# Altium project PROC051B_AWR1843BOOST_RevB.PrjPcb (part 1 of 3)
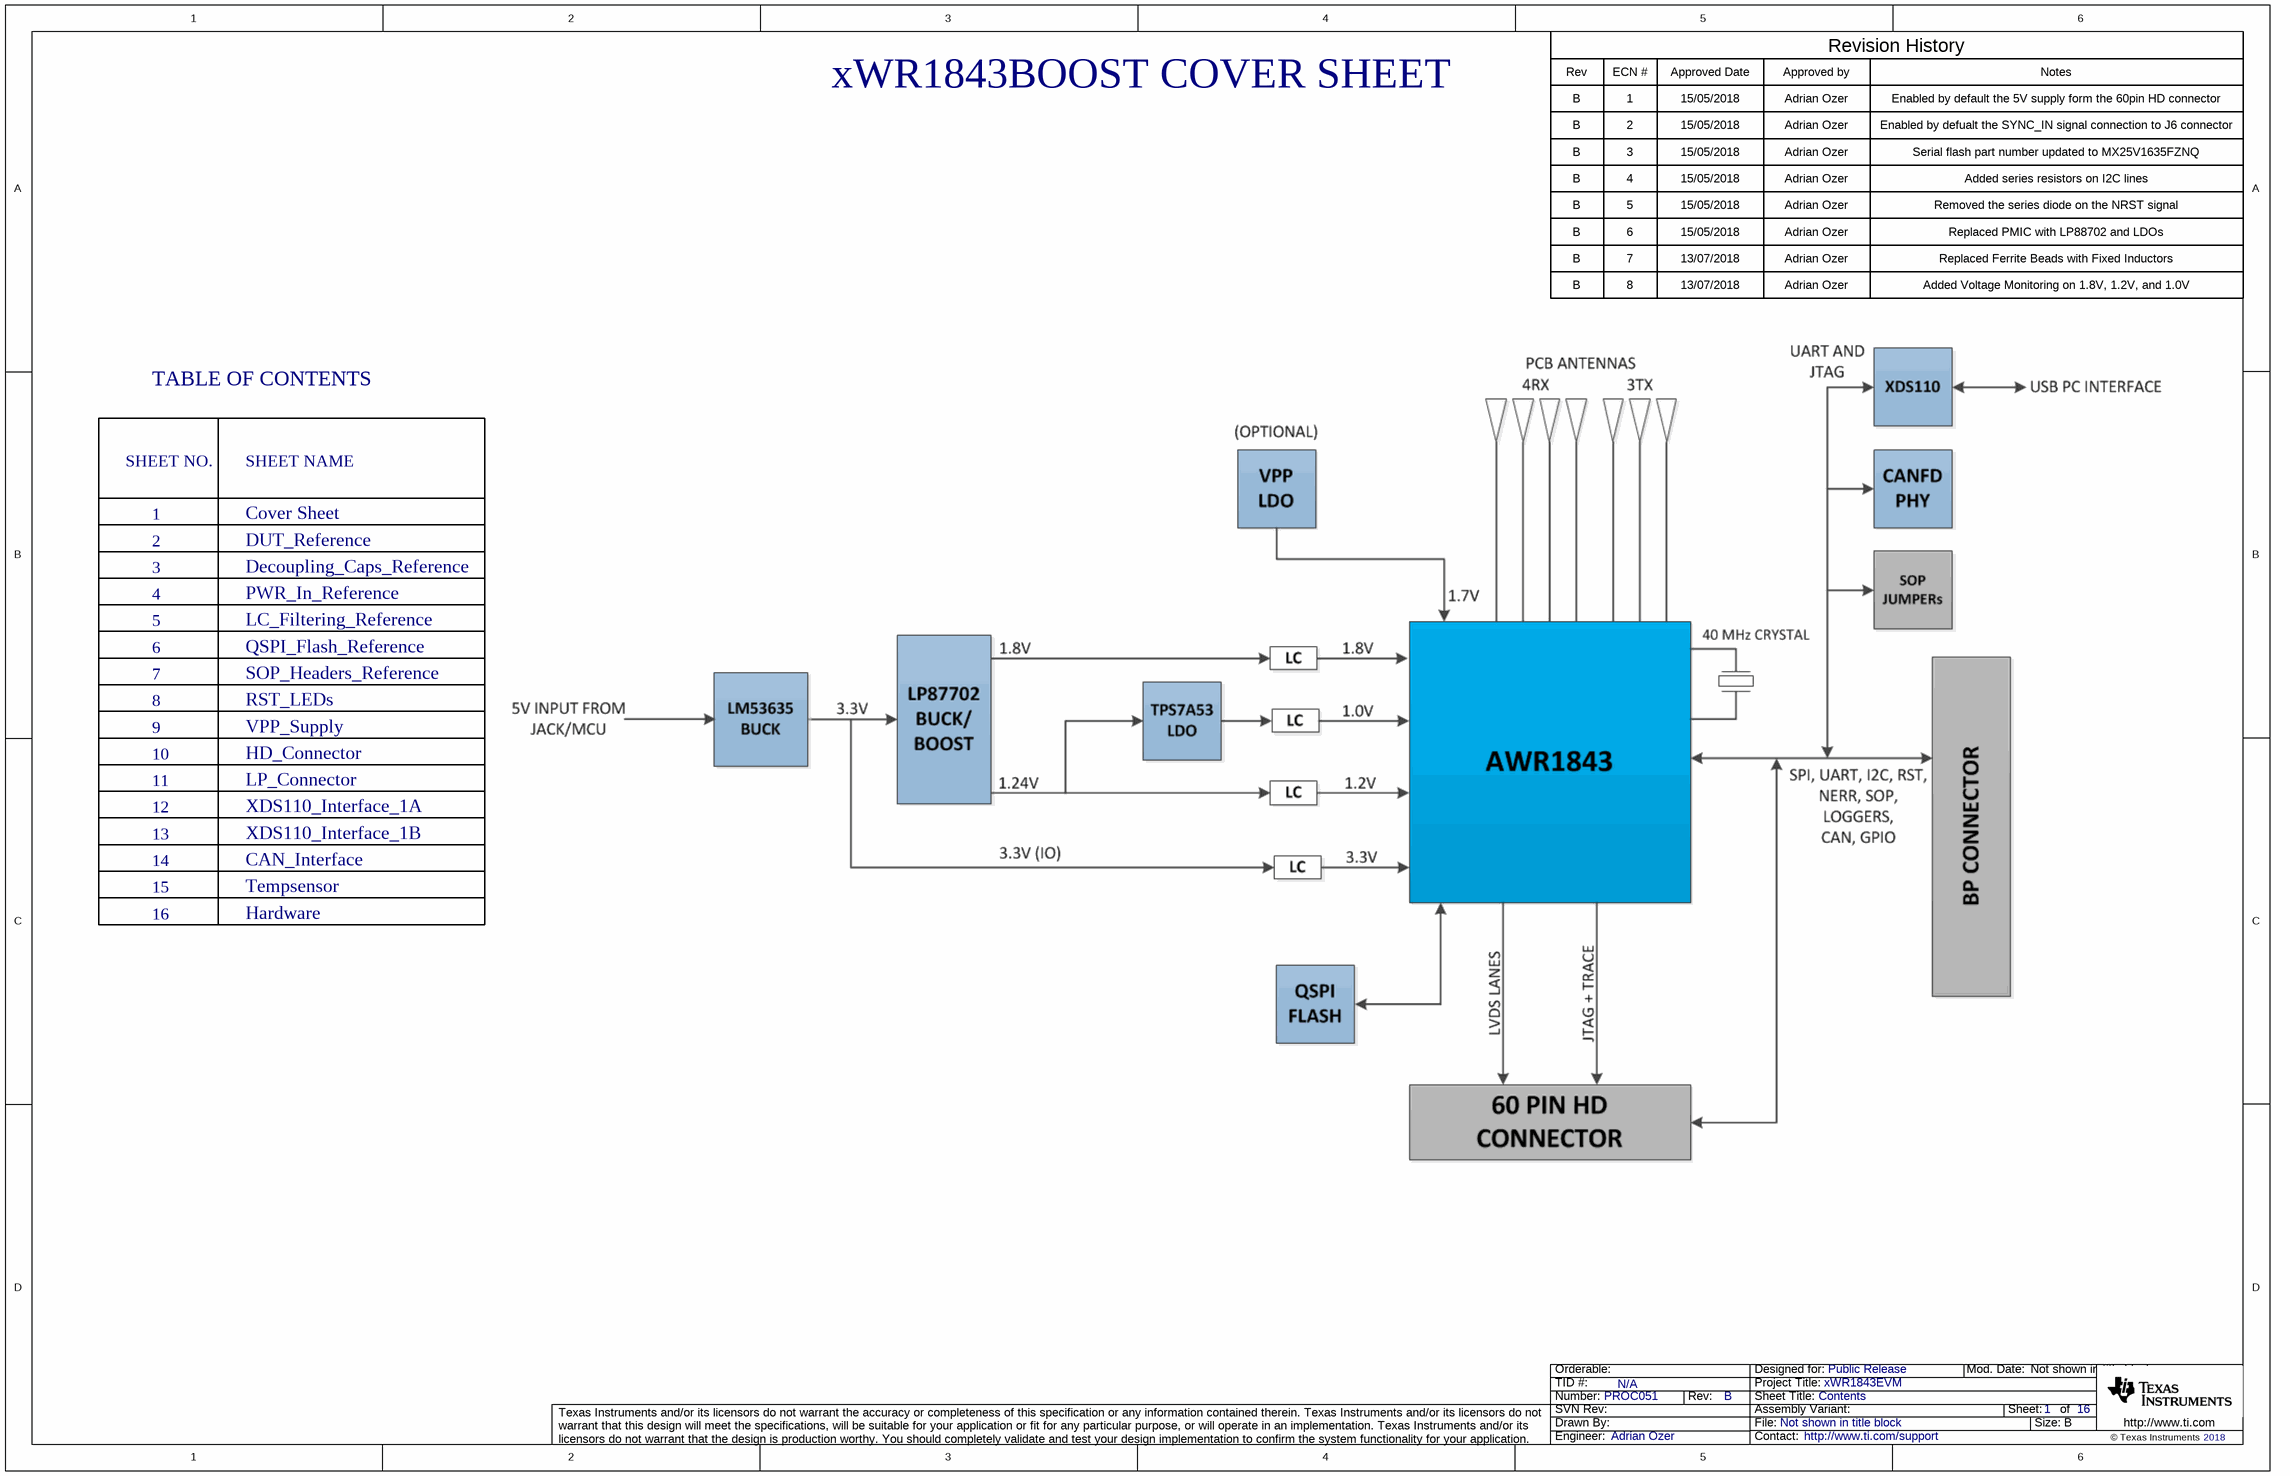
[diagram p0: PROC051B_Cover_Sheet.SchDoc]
CopyrightYear: 2018; PCB_Layout: TESSOLVE; PCB_Rev: B; PRJ_Customer: Public Release; PRJ_Engineer: Adrian Ozer; PRJ_Number: PROC051; PRJ_Title: xWR1843EVM; SCH_Rev: B; TechSupport: http://www.ti.com/support; TID: N/A
16 sheets, 379 parts. Net scope: flat (ports and power ports of the same name join across sheets).
Board file: PROC051B_PCB.PcbDoc
Sheets:
  PROC051B_Cover_Sheet.SchDoc
  PROC051B_DUT_Reference.SchDoc
  PROC051B_Decoupling_Caps_Reference.SchDoc
  PROC051B_PWR_In_Reference.SchDoc
  PROC051B_LC_Filtering_Reference.SchDoc
  PROC051B_QSPI_Flash_Reference.SchDoc
  PROC051B_SOP_Headers_Reference.SchDoc
  PROC051B_RST_LEDs.SchDoc
  PROC051B_VPP_Supply.SchDoc
  PROC051B_HD Connector.SchDoc
  PROC051B_LP Connector.SchDoc
  PROC051B_XDS110 Interface_1A.SchDoc
  PROC051B_XDS110 Interface_1B.SchDoc
  PROC051B_CAN_Interface.SchDoc
  PROC051B_Tempsensor.SchDoc
  PROC051B_Hardware.SchDoc

## Sheet PROC051B_Cover_Sheet.SchDoc: Contents
size 431 x 279 mm; Date: Not shown in title block; ApprovedBy: Not shown in title block; CheckedBy: Not shown in title block; Author: Not shown in title block; CompanyName: Not shown in title block; Engineer: Not shown in title block; Organization: Not shown in title block; Address1: Not shown in title block; Address2: Not shown in title block; Address3: Not shown in title block; Address4: Not shown in title block; DocumentNumber: 1; Revision: Use project parameter SCH_Rev; SheetNumber: 1; SheetTotal: 16; PageSetup: Record=PageOptions¦CenterHorizontal=True¦CenterVertical=True¦PrintScale=0.64¦XCorrection=1.00¦YCorrection=1.00¦PrintKind=0¦BorderSize=5000000¦LeftOffset=0¦BottomOffset=0¦Orientation=2¦PaperLength=1000¦PaperWidth=1000¦Scale=100¦PaperSource=15¦PrintQuality=600¦MediaType=1¦DitherType=10¦PrintScaleMode=1¦PaperKind=Letter

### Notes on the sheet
- xWR1843BOOST COVER SHEET
- Rev
- B
- ECN #
- 1
- Approved Date
- 15/05/2018
- Approved by
- Adrian Ozer
- Revision History
- Notes
- Enabled by default the 5V supply form the 60pin HD connector
- 2
- 3
- Enabled by defualt the SYNC_IN signal connection to J6 connector
- Serial flash part number updated to MX25V1635FZNQ
- 4
- 5
- 6
- Added series resistors on I2C lines
- Removed the series diode on the NRST signal
- Replaced PMIC with LP88702 and LDOs
- 7
- 8
- 13/07/2018
- Replaced Ferrite Beads with Fixed Inductors
- Added Voltage Monitoring on 1.8V, 1.2V, and 1.0V
- TABLE OF CONTENTS
- SHEET NO.
- SHEET NAME
- Cover Sheet
- DUT_Reference
- Decoupling_Caps_Reference
- PWR_In_Reference
- LC_Filtering_Reference
- QSPI_Flash_Reference
- SOP_Headers_Reference
- 9
- 10
- RST_LEDs
- VPP_Supply
- HD_Connector
- 11
- 12
- LP_Connector
- XDS110_Interface_1A
- 13
- 15
- 14
- XDS110_Interface_1B
- Tempsensor
- CAN_Interface
- 16
- Hardware

## Sheet PROC051B_DUT_Reference.SchDoc: DUT
size 431 x 279 mm; Date: Not shown in title block; ApprovedBy: Not shown in title block; CheckedBy: Not shown in title block; Author: Not shown in title block; CompanyName: Not shown in title block; Engineer: Not shown in title block; Organization: Not shown in title block; Address1: Not shown in title block; Address2: Not shown in title block; Address3: Not shown in title block; Address4: Not shown in title block; DocumentNumber: 2; Revision: Use project parameter SCH_Rev; SheetNumber: 2; SheetTotal: 16; PageSetup: Record=PageOptions¦CenterHorizontal=True¦CenterVertical=True¦PrintScale=1.00¦XCorrection=1.00¦YCorrection=1.00¦PrintKind=0¦BorderSize=5000000¦LeftOffset=0¦BottomOffset=0¦Orientation=2¦PaperLength=1000¦PaperWidth=1000¦Scale=100¦PaperSource=15¦PrintQuality=-3¦MediaType=1¦DitherType=10¦PrintScaleMode=1¦PaperKind=Letter¦PaperIndex=1
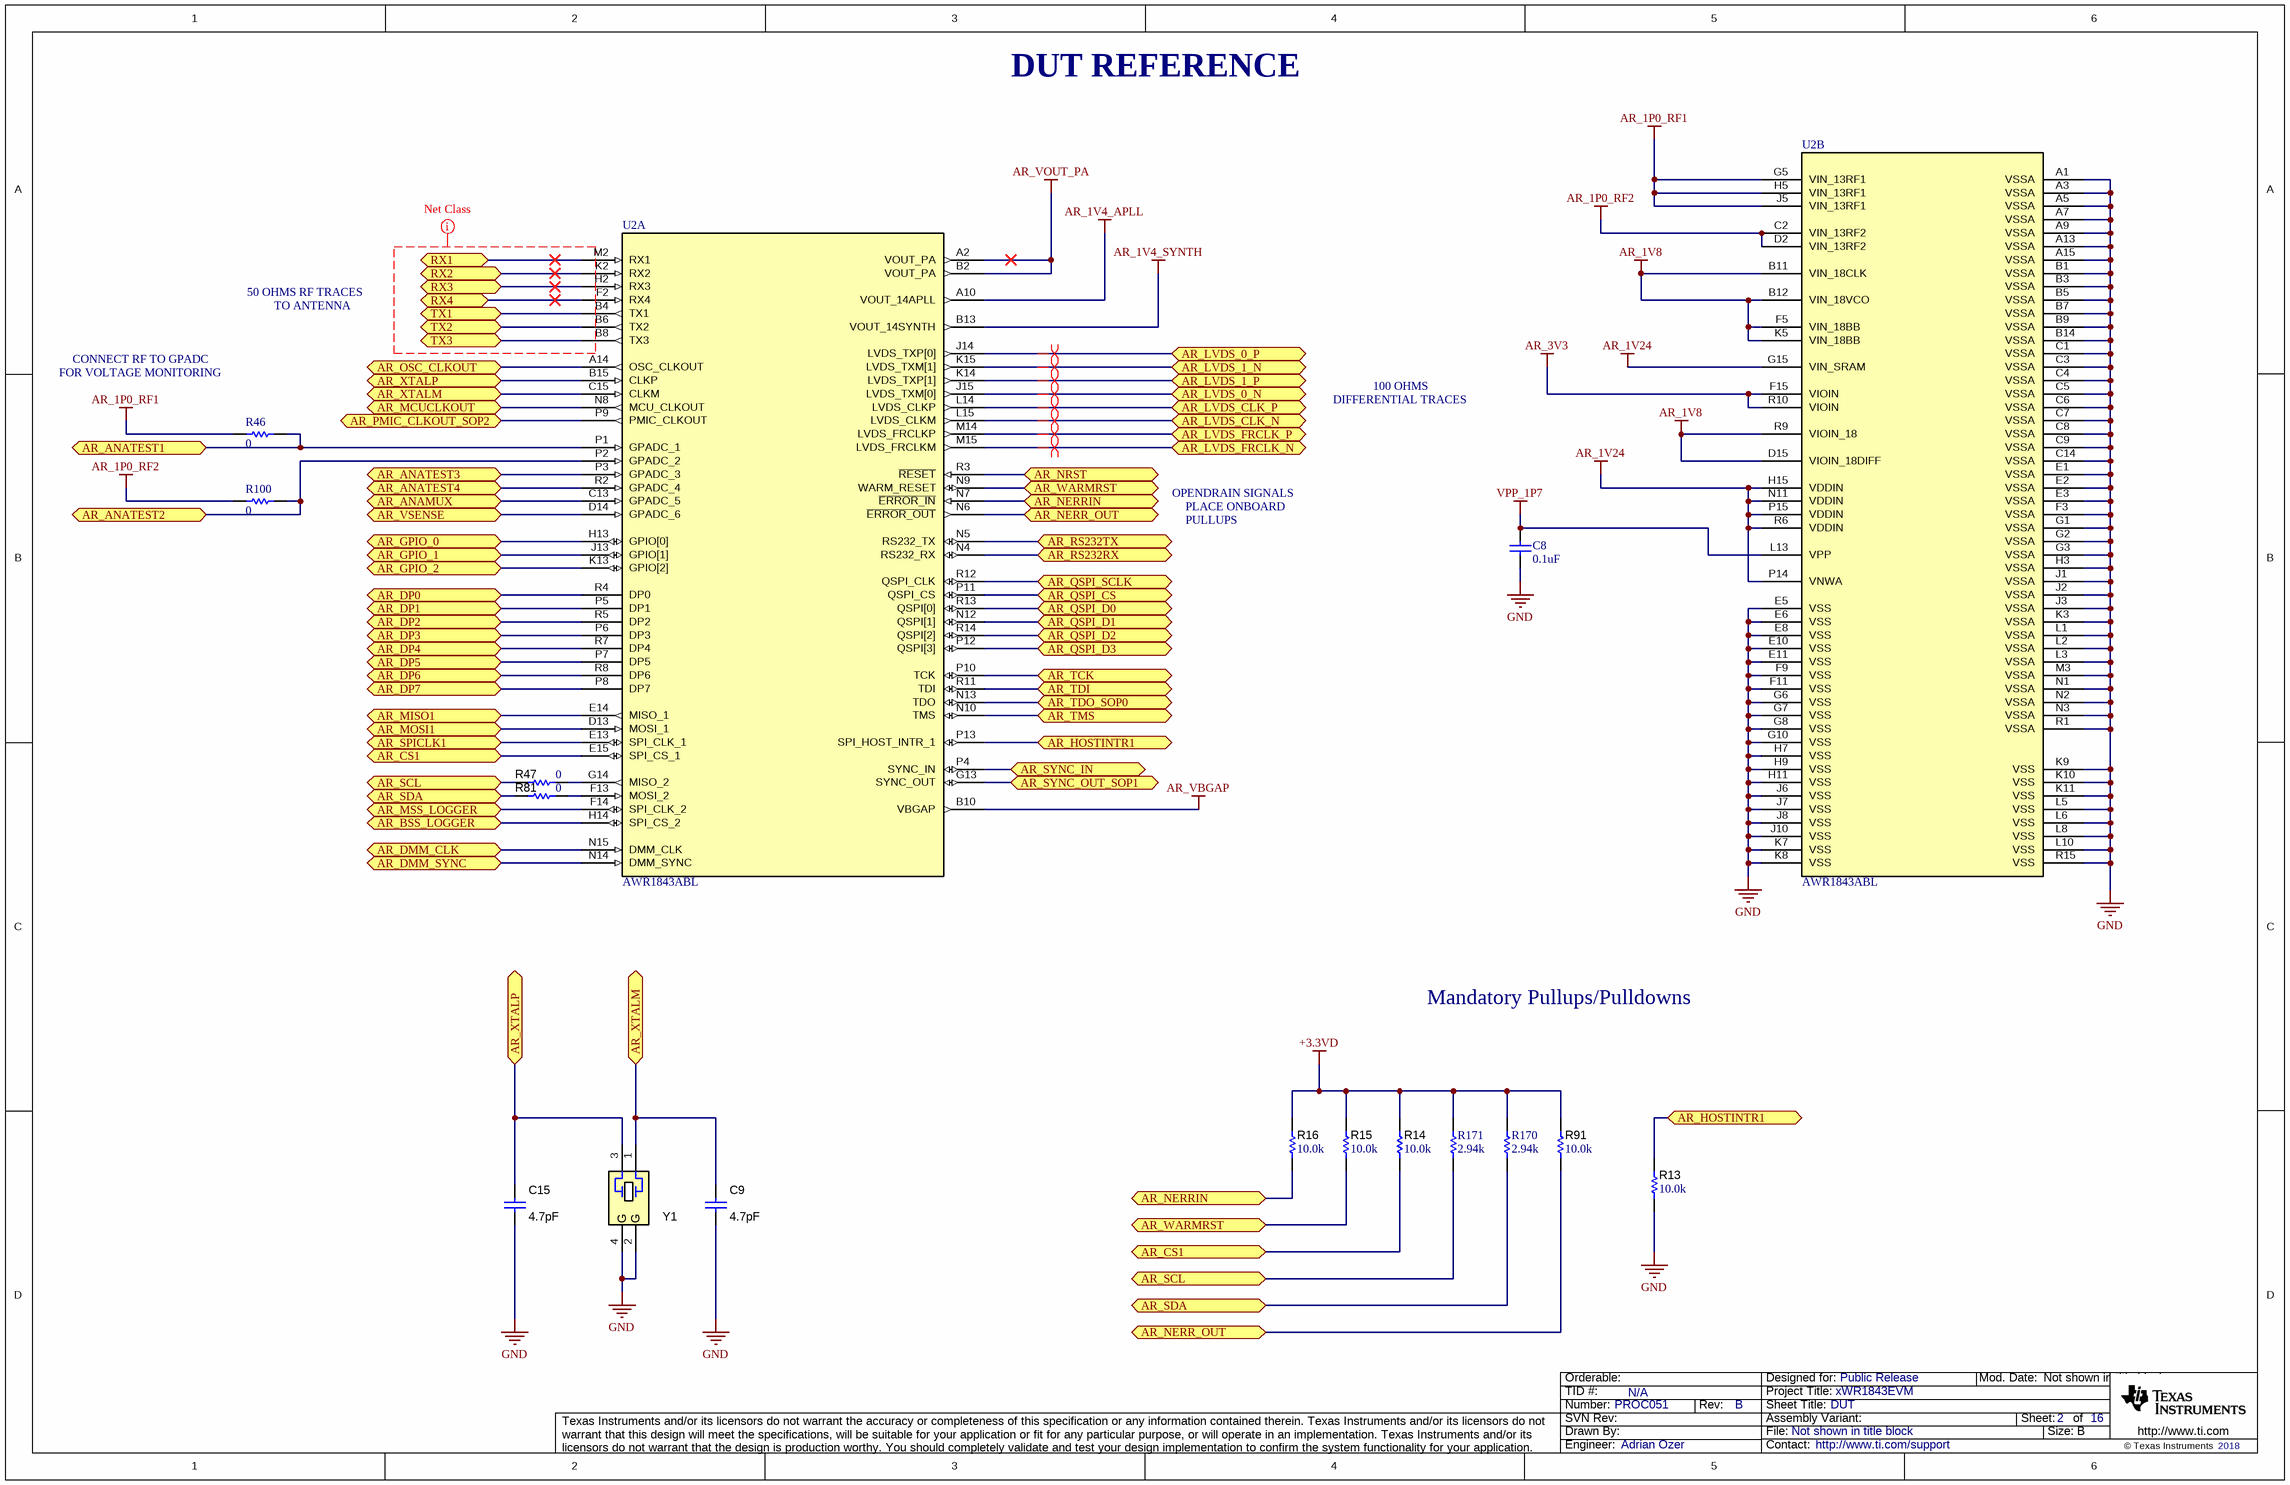
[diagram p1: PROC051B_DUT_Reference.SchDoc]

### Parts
C8  ValueDisplayed: 0.1uF  [0201]  (hidden comment: GRM033C71A104KE14D)
C9  ValueDisplayed: 4.7pF  [0402L]  (hidden comment: GJM1555C1H4R7BB01D)
C15  ValueDisplayed: 4.7pF  [0402L]  (hidden comment: GJM1555C1H4R7BB01D)
R13  ValueDisplayed: 10.0k  [0402L]  (hidden comment: CRCW040210K0FKED)
R14  ValueDisplayed: 10.0k  [0402L]  (hidden comment: CRCW040210K0FKED)
R15  ValueDisplayed: 10.0k  [0402L]  (hidden comment: CRCW040210K0FKED)
R16  ValueDisplayed: 10.0k  [0402L]  (hidden comment: CRCW040210K0FKED)
R46  ValueDisplayed: 0  [0402]  (hidden comment: CRCW04020000Z0ED)
R47  value 0  [0402L]  (hidden comment: Resistor)
R81  value 0  [0402L]  (hidden comment: Resistor)
R91  ValueDisplayed: 10.0k  [0402L]  (hidden comment: CRCW040210K0FKED)
R100  ValueDisplayed: 0  [0402]  (hidden comment: CRCW04020000Z0ED)
R170  ValueDisplayed: 2.94k  [0402]  (hidden comment: CRCW04022K94FKED)
R171  ValueDisplayed: 2.94k  [0402]  (hidden comment: CRCW04022K94FKED)
U2  AWR1843ABL  [ABL0161B]  (parts A,B of 2)
Y1  CX3225SA40000D0PTWCC  [Kyocera_CX3225SA]  (value not drawn)

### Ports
AR_ANAMUX, AR_ANATEST1, AR_ANATEST2, AR_ANATEST3, AR_ANATEST4, AR_BSS_LOGGER, AR_CS1, AR_DMM_CLK, AR_DMM_SYNC, AR_DP0, AR_DP1, AR_DP2, AR_DP3, AR_DP4, AR_DP5, AR_DP6, AR_DP7, AR_GPIO_0, AR_GPIO_1, AR_GPIO_2, AR_HOSTINTR1, AR_LVDS_0_N, AR_LVDS_0_P, AR_LVDS_1_N, AR_LVDS_1_P, AR_LVDS_CLK_N, AR_LVDS_CLK_P, AR_LVDS_FRCLK_N, AR_LVDS_FRCLK_P, AR_MCUCLKOUT, AR_MISO1, AR_MOSI1, AR_MSS_LOGGER, AR_NERR_OUT, AR_NERRIN, AR_NRST, AR_OSC_CLKOUT, AR_PMIC_CLKOUT_SOP2, AR_QSPI_CS, AR_QSPI_D0, AR_QSPI_D1, AR_QSPI_D2, AR_QSPI_D3, AR_QSPI_SCLK, AR_RS232RX, AR_RS232TX, AR_SCL, AR_SDA, AR_SPICLK1, AR_SYNC_IN, AR_SYNC_OUT_SOP1, AR_TCK, AR_TDI, AR_TDO_SOP0, AR_TMS, AR_VSENSE, AR_WARMRST, AR_XTALM, AR_XTALP, RX1, RX2, RX3, RX4, TX1, TX2, TX3

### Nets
+3.3VD: R14.2 R15.2 R16.2 R91.2 R170.2 R171.2
AR_1P0_RF1: R46.2 U2.G5(VIN_13RF1) U2.H5(VIN_13RF1) U2.J5(VIN_13RF1)
AR_1P0_RF2: R100.2 U2.C2(VIN_13RF2) U2.D2(VIN_13RF2)
AR_1V4_APLL: U2.A10(VOUT_14APLL)
AR_1V4_SYNTH: U2.B13(VOUT_14SYNTH)
AR_1V8: U2.B11(VIN_18CLK) U2.B12(VIN_18VCO) U2.D15(VIOIN_18DIFF) U2.F5(VIN_18BB) U2.K5(VIN_18BB) U2.R9(VIOIN_18)
AR_1V24: U2.G15(VIN_SRAM) U2.H15(VDDIN) U2.N11(VDDIN) U2.P14(VNWA) U2.P15(VDDIN) U2.R6(VDDIN)
AR_3V3: U2.F15(VIOIN) U2.R10(VIOIN)
AR_VBGAP: U2.B10(VBGAP)
AR_VOUT_PA: U2.A2(VOUT_PA) U2.B2(VOUT_PA)
GND: C8.2 C9.1 C15.1 R13.1 U2.A1(VSSA) U2.A3(VSSA) U2.A5(VSSA) U2.A7(VSSA) U2.A9(VSSA) U2.A13(VSSA) U2.A15(VSSA) U2.B1(VSSA) U2.B3(VSSA) U2.B5(VSSA) U2.B7(VSSA) U2.B9(VSSA) U2.B14(VSSA) U2.C1(VSSA) U2.C3(VSSA) U2.C4(VSSA) U2.C5(VSSA) U2.C6(VSSA) U2.C7(VSSA) U2.C8(VSSA) U2.C9(VSSA) U2.C14(VSSA) U2.E1(VSSA) U2.E2(VSSA) U2.E3(VSSA) U2.E5(VSS) U2.E6(VSS) U2.E8(VSS) U2.E10(VSS) U2.E11(VSS) U2.F3(VSSA) U2.F9(VSS) U2.F11(VSS) U2.G1(VSSA) U2.G2(VSSA) U2.G3(VSSA) U2.G6(VSS) U2.G7(VSS) U2.G8(VSS) U2.G10(VSS) U2.H3(VSSA) U2.H7(VSS) U2.H9(VSS) U2.H11(VSS) U2.J1(VSSA) U2.J2(VSSA) U2.J3(VSSA) U2.J6(VSS) U2.J7(VSS) U2.J8(VSS) U2.J10(VSS) U2.K3(VSSA) U2.K7(VSS) U2.K8(VSS) U2.K9(VSS) U2.K10(VSS) U2.K11(VSS) U2.L1(VSSA) U2.L2(VSSA) U2.L3(VSSA) U2.L5(VSS) U2.L6(VSS) U2.L8(VSS) U2.L10(VSS) U2.M3(VSSA) U2.N1(VSSA) U2.N2(VSSA) U2.N3(VSSA) U2.R1(VSSA) U2.R15(VSS) Y1.2(GND) Y1.4(GND)
VPP_1P7: C8.1 U2.L13(VPP)
AR_ANAMUX: U2.C13(GPADC_5) ; port AR_ANAMUX
AR_ANATEST1: R46.1 U2.P1(GPADC_1) ; port AR_ANATEST1
AR_ANATEST2: R100.1 U2.P2(GPADC_2) ; port AR_ANATEST2
AR_ANATEST3: U2.P3(GPADC_3) ; port AR_ANATEST3
AR_ANATEST4: U2.R2(GPADC_4) ; port AR_ANATEST4
AR_BSS_LOGGER: U2.H14(SPI_CS_2) ; port AR_BSS_LOGGER
AR_CS1: R14.1 U2.E15(SPI_CS_1) ; port AR_CS1
AR_DMM_CLK: U2.N15(DMM_CLK) ; port AR_DMM_CLK
AR_DMM_SYNC: U2.N14(DMM_SYNC) ; port AR_DMM_SYNC
AR_DP0: U2.R4(DP0) ; port AR_DP0
AR_DP1: U2.P5(DP1) ; port AR_DP1
AR_DP2: U2.R5(DP2) ; port AR_DP2
AR_DP3: U2.P6(DP3) ; port AR_DP3
AR_DP4: U2.R7(DP4) ; port AR_DP4
AR_DP5: U2.P7(DP5) ; port AR_DP5
AR_DP6: U2.R8(DP6) ; port AR_DP6
AR_DP7: U2.P8(DP7) ; port AR_DP7
AR_GPIO_0: U2.H13(GPIO[0]) ; port AR_GPIO_0
AR_GPIO_1: U2.J13(GPIO[1]) ; port AR_GPIO_1
AR_GPIO_2: U2.K13(GPIO[2]) ; port AR_GPIO_2
AR_HOSTINTR1: R13.2 U2.P13(SPI_HOST_INTR_1) ; port AR_HOSTINTR1
AR_LVDS_0_N: U2.J15(LVDS_TXM[0]) ; port AR_LVDS_0_N
AR_LVDS_0_P: U2.J14(LVDS_TXP[0]) ; port AR_LVDS_0_P
AR_LVDS_1_N: U2.K15(LVDS_TXM[1]) ; port AR_LVDS_1_N
AR_LVDS_1_P: U2.K14(LVDS_TXP[1]) ; port AR_LVDS_1_P
AR_LVDS_CLK_N: U2.L15(LVDS_CLKM) ; port AR_LVDS_CLK_N
AR_LVDS_CLK_P: U2.L14(LVDS_CLKP) ; port AR_LVDS_CLK_P
AR_LVDS_FRCLK_N: U2.M15(LVDS_FRCLKM) ; port AR_LVDS_FRCLK_N
AR_LVDS_FRCLK_P: U2.M14(LVDS_FRCLKP) ; port AR_LVDS_FRCLK_P
AR_MCUCLKOUT: U2.N8(MCU_CLKOUT) ; port AR_MCUCLKOUT
AR_MISO1: U2.E14(MISO_1) ; port AR_MISO1
AR_MOSI1: U2.D13(MOSI_1) ; port AR_MOSI1
AR_MSS_LOGGER: U2.F14(SPI_CLK_2) ; port AR_MSS_LOGGER
AR_NERR_OUT: R91.1 U2.N6(~{ERROR_OUT}) ; port AR_NERR_OUT
AR_NERRIN: R16.1 U2.N7(~{ERROR_IN}) ; port AR_NERRIN
AR_NRST: U2.R3(~{RESET}) ; port AR_NRST
AR_OSC_CLKOUT: U2.A14(OSC_CLKOUT) ; port AR_OSC_CLKOUT
AR_PMIC_CLKOUT_SOP2: U2.P9(PMIC_CLKOUT) ; port AR_PMIC_CLKOUT_SOP2
AR_QSPI_CS: U2.P11(QSPI_CS) ; port AR_QSPI_CS
AR_QSPI_D0: U2.R13(QSPI[0]) ; port AR_QSPI_D0
AR_QSPI_D1: U2.N12(QSPI[1]) ; port AR_QSPI_D1
AR_QSPI_D2: U2.R14(QSPI[2]) ; port AR_QSPI_D2
AR_QSPI_D3: U2.P12(QSPI[3]) ; port AR_QSPI_D3
AR_QSPI_SCLK: U2.R12(QSPI_CLK) ; port AR_QSPI_SCLK
AR_RS232RX: U2.N4(RS232_RX) ; port AR_RS232RX
AR_RS232TX: U2.N5(RS232_TX) ; port AR_RS232TX
AR_SCL: R47.2 R171.1 ; port AR_SCL
AR_SDA: R81.2 R170.1 ; port AR_SDA
AR_SPICLK1: U2.E13(SPI_CLK_1) ; port AR_SPICLK1
AR_SYNC_IN: U2.P4(SYNC_IN) ; port AR_SYNC_IN
AR_SYNC_OUT_SOP1: U2.G13(SYNC_OUT) ; port AR_SYNC_OUT_SOP1
AR_TCK: U2.P10(TCK) ; port AR_TCK
AR_TDI: U2.R11(TDI) ; port AR_TDI
AR_TDO_SOP0: U2.N13(TDO) ; port AR_TDO_SOP0
AR_TMS: U2.N10(TMS) ; port AR_TMS
AR_VSENSE: U2.D14(GPADC_6) ; port AR_VSENSE
AR_WARMRST: R15.1 U2.N9(WARM_RESET) ; port AR_WARMRST
AR_XTALM: C9.2 U2.C15(CLKM) Y1.1 ; port AR_XTALM
AR_XTALP: C15.2 U2.B15(CLKP) Y1.3 ; port AR_XTALP
RX1: U2.M2(RX1) ; port RX1
RX2: U2.K2(RX2) ; port RX2
RX3: U2.H2(RX3) ; port RX3
RX4: U2.F2(RX4) ; port RX4
TX1: U2.B4(TX1) ; port TX1
TX2: U2.B6(TX2) ; port TX2
TX3: U2.B8(TX3) ; port TX3
NetR47_1: R47.1 U2.G14(MISO_2)
NetR81_1: R81.1 U2.F13(MOSI_2)

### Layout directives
differential pair: AR_LVDS_0_N, AR_LVDS_0_P, AR_LVDS_1_N, AR_LVDS_1_P, AR_LVDS_CLK_N, AR_LVDS_CLK_P, AR_LVDS_FRCLK_N, AR_LVDS_FRCLK_P
net class RX_TX: (no net found under the mark)

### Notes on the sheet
- DUT REFERENCE
- 50 OHMS RF TRACES
- CONNECT RF TO GPADC
- TO ANTENNA
- FOR VOLTAGE MONITORING
- DIFFERENTIAL TRACES
- 100 OHMS
- OPENDRAIN SIGNALS
- PLACE ONBOARD
- PULLUPS
- Mandatory Pullups/Pulldowns

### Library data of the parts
C8 = CMP-0064969-1: CAP, CERM, 0.1 uF, 10 V,+/- 10%, X7S, 0201; Manufacturer: MuRata; TaMin_C: -55°C; Polarized: N; SizeAreaWB_mm2: 2.08; Value1: Unknown; U/M: EA; Value: 0.1uF; TaMax_C: 125°C; SizeZ_mm: 0.26; SizeX_mm: 0.6; SizeY_mm: 0.3; Value2: 10V; SizeArea_mm2: 0.18; CompType: Capacitor; Cap_F: 100nF; AEC Category: Q200
C9 C15 = CMP-0006367-2: CAP, CERM, 4.7 pF, 50 V, +/- 2%, C0G/NP0, 0402; Manufacturer: MuRata; TaMin_C: -55°C; Polarized: N; SizeAreaWB_mm2: 3; Value1: Unknown; U/M: EA; Value: 4.7pF; TaMax_C: 125°C; SizeZ_mm: 0.6; SizeX_mm: 1; SizeY_mm: 0.5; Cap_Case: 0402; Value2: 50V; CompType: Capacitor; AEC Category: Q200
R13-R16 R91 = CMP-0025958-3: RES, 10.0 k, 1%, 0.063 W, AEC-Q200 Grade 0, 0402; Manufacturer: Vishay-Dale; Power_W: 63mW; TempCo: 100 ppm/C; Value_Code: 10k0; Value: 10.0k; EIA_Code: E96; Res_ohm: 10k; SizeX_mm: 1; SizeY_mm: 0.5; SizeZ_mm: 0.6; Value2: 0.063W; AEC Qualified: Y; VDC_V: 50V; AEC Category: Q200; AEC Grade: 0
R46 R100 = CMP-0026822-3: RES, 0, 5%, 0.063 W, AEC-Q200 Grade 0, 0402; Manufacturer: Vishay-Dale; Power_W: 63mW; TempCo: 200 ppm/C; Value_Code: 0000; Value: 0; EIA_Code: E24; SizeX_mm: 1; SizeY_mm: 0.5; SizeZ_mm: 0.6; Value2: 0.063W; CompType: Resistor; AEC Qualified: Y; VDC_V: 50V; AEC Category: Q200
R47 R81 = CMP-0026822-3: RES, 0, 5%, 0.063 W, AEC-Q200 Grade 0, 0402; PartNumber: CRCW04020000Z0ED; Manufacturer: Vishay-Dale; Value_Code: 0000; Power_W: 63mW; Value2: 0.063W; VDC_V: 50V; TempCo: 200 ppm/C; EIA_Code: E24; AEC Category: Q200; AEC Qualified: Y; SizeArea_mm2: 0.5; SizeX_mm: 1; SizeZ_mm: 0.6
R170 R171 = CMP-0026244-2: RES, 2.94 k, 1%, 0.063 W, AEC-Q200 Grade 0, 0402; Manufacturer: Vishay-Dale; Power_W: 63mW; TempCo: 100 ppm/C; Value_Code: 2k94; Value: 2.94k; EIA_Code: E96; SizeX_mm: 1; SizeY_mm: 0.5; SizeZ_mm: 0.6; Value2: 0.063W; AEC Qualified: Y; VDC_V: 50V; AEC Category: Q200; AEC Grade: 0
U2 = CMP-0078239-1: AWR1843ABL, ABL0161B (FCBGA-161); Manufacturer: Texas Instruments; AEC Qualified: N; SizeArea_mm2: 108.16; CompType: IC; SizeAreaWB_mm2: 153.76; AEC Category: Q200; SizeY_mm: 10.4; SizeZ_mm: 1.17
Y1 = CMP-0004694-3: Crystal, 40 MHz, 8pF, SMD; Manufacturer: Kyocera; TaMin_C: -40°C; Frequency Stability: +/-200ppm; SizeAreaWB_mm2: 14.7; Frequency_Fixed: 40MHz; TaMax_C: 125°C; SizeZ_mm: 0.8; SizeX_mm: 2.5; SizeY_mm: 3.2; SizeArea_mm2: 8

## Sheet PROC051B_Decoupling_Caps_Reference.SchDoc: Decoupling_caps
size 431 x 279 mm; Date: Not shown in title block; ApprovedBy: Not shown in title block; CheckedBy: Not shown in title block; Author: Not shown in title block; CompanyName: Not shown in title block; Engineer: Not shown in title block; Organization: Not shown in title block; Address1: Not shown in title block; Address2: Not shown in title block; Address3: Not shown in title block; Address4: Not shown in title block; DocumentNumber: 3; Revision: Use project parameter SCH_Rev; SheetNumber: 3; SheetTotal: 16; PageSetup: Record=PageOptions¦CenterHorizontal=True¦CenterVertical=True¦PrintScale=1.00¦XCorrection=1.00¦YCorrection=1.00¦PrintKind=0¦BorderSize=5000000¦LeftOffset=0¦BottomOffset=0¦Orientation=2¦PaperLength=1000¦PaperWidth=1000¦Scale=100¦PaperSource=15¦PrintQuality=600¦MediaType=1¦DitherType=10¦PaperKind=Letter¦PrintScaleMode=1
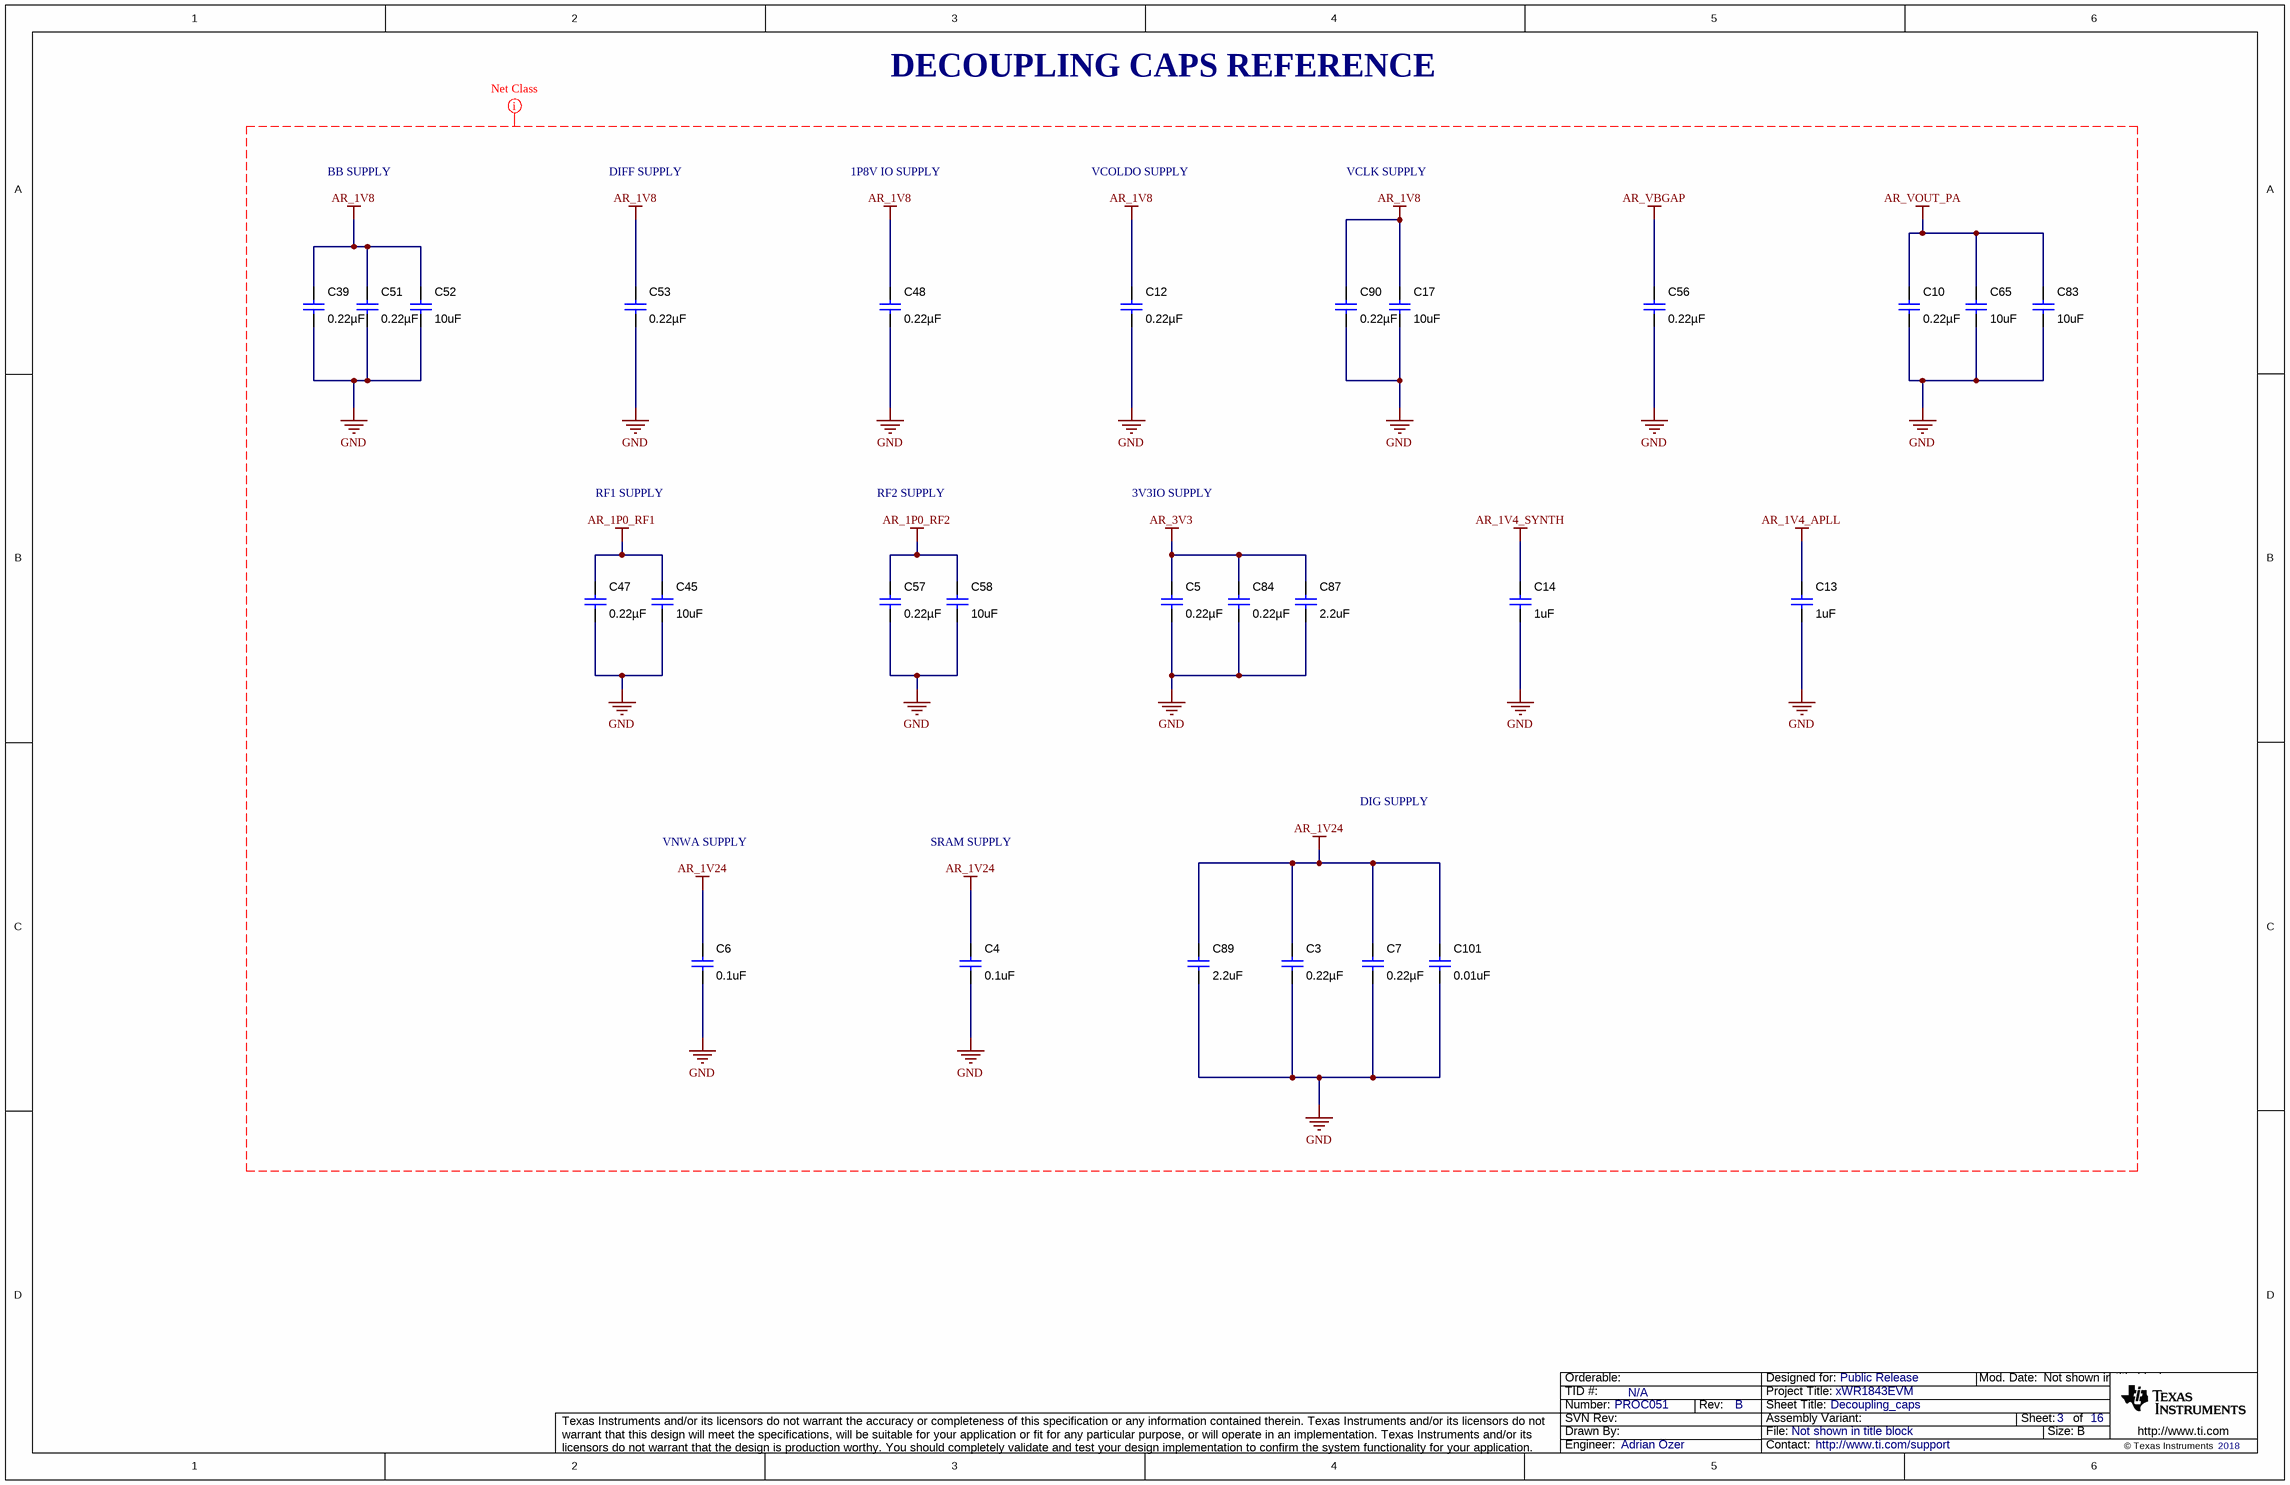
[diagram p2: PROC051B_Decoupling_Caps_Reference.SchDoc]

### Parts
C3  ValueDisplayed: 0.22µF  [0402L]  (hidden comment: GCM155R71C224KE02D)
C4  ValueDisplayed: 0.1uF  [0402L]  (hidden comment: GCM155R71C104KA55D)
C5  ValueDisplayed: 0.22µF  [0402L]  (hidden comment: GCM155R71C224KE02D)
C6  ValueDisplayed: 0.1uF  [0402L]  (hidden comment: GCM155R71C104KA55D)
C7  ValueDisplayed: 0.22µF  [0402L]  (hidden comment: GCM155R71C224KE02D)
C10  ValueDisplayed: 0.22µF  [0402L]  (hidden comment: GCM155R71C224KE02D)
C12  ValueDisplayed: 0.22µF  [0402L]  (hidden comment: GCM155R71C224KE02D)
C13  ValueDisplayed: 1uF  [0603]  (hidden comment: GCM188R71C105KA64D)
C14  ValueDisplayed: 1uF  [0603]  (hidden comment: GCM188R71C105KA64D)
C17  ValueDisplayed: 10uF  [0805_HV]  (hidden comment: GCM21BR71A106KE22L)
C39  ValueDisplayed: 0.22µF  [0402L]  (hidden comment: GCM155R71C224KE02D)
C45  ValueDisplayed: 10uF  [0805_HV]  (hidden comment: GCM21BR71A106KE22L)
C47  ValueDisplayed: 0.22µF  [0402L]  (hidden comment: GCM155R71C224KE02D)
C48  ValueDisplayed: 0.22µF  [0402L]  (hidden comment: GCM155R71C224KE02D)
C51  ValueDisplayed: 0.22µF  [0402L]  (hidden comment: GCM155R71C224KE02D)
C52  ValueDisplayed: 10uF  [0805_HV]  (hidden comment: GCM21BR71A106KE22L)
C53  ValueDisplayed: 0.22µF  [0402L]  (hidden comment: GCM155R71C224KE02D)
C56  ValueDisplayed: 0.22µF  [0402L]  (hidden comment: GCM155R71C224KE02D)
C57  ValueDisplayed: 0.22µF  [0402L]  (hidden comment: GCM155R71C224KE02D)
C58  ValueDisplayed: 10uF  [0805_HV]  (hidden comment: GCM21BR71A106KE22L)
C65  ValueDisplayed: 10uF  [0805_HV]  (hidden comment: GCM21BR71A106KE22L)
C83  ValueDisplayed: 10uF  [0805_HV]  (hidden comment: GCM21BR71A106KE22L)
C84  ValueDisplayed: 0.22µF  [0402L]  (hidden comment: GCM155R71C224KE02D)
C87  ValueDisplayed: 2.2uF  [0603]  (hidden comment: GCM188R70J225KE22D)
C89  ValueDisplayed: 2.2uF  [0603]  (hidden comment: GCM188R70J225KE22D)
C90  ValueDisplayed: 0.22µF  [0402L]  (hidden comment: GCM155R71C224KE02D)
C101  ValueDisplayed: 0.01uF  [0402L]  (hidden comment: GCM155R71E103KA37D)

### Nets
AR_1P0_RF1: C45.2 C47.2
AR_1P0_RF2: C57.2 C58.2
AR_1V4_APLL: C13.2
AR_1V4_SYNTH: C14.2
AR_1V8: C12.2 C17.2 C39.2 C48.2 C51.2 C52.2 C53.2 C90.2
AR_1V24: C3.2 C4.2 C6.2 C7.2 C89.2 C101.1
AR_3V3: C5.2 C84.2 C87.2
AR_VBGAP: C56.2
AR_VOUT_PA: C10.2 C65.2 C83.2
GND: C3.1 C4.1 C5.1 C6.1 C7.1 C10.1 C12.1 C13.1 C14.1 C17.1 C39.1 C45.1 C47.1 C48.1 C51.1 C52.1 C53.1 C56.1 C57.1 C58.1 C65.1 C83.1 C84.1 C87.1 C89.1 C90.1 C101.2

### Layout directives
net class PWR: AR_1P0_RF1, AR_1P0_RF2, AR_1V4_APLL, AR_1V4_SYNTH, AR_1V8, AR_1V24, AR_3V3, AR_VBGAP, AR_VOUT_PA, GND

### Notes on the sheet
- DECOUPLING CAPS REFERENCE
- BB SUPPLY
- DIFF SUPPLY
- 1P8V IO SUPPLY
- VCOLDO SUPPLY
- VCLK SUPPLY
- RF1 SUPPLY
- RF2 SUPPLY
- 3V3IO SUPPLY
- DIG SUPPLY
- VNWA SUPPLY
- SRAM SUPPLY

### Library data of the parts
C3 C5 C7 C10 C12 C39 C47 C48 C51 C53 C56 C57 C84 C90 = CMP-0078265-1: CAP, CERM, 0.22 µF, 16 V,+/- 10%, X7R, AEC-Q200 Grade 1, 0402; Manufacturer: MuRata; TaMin_C: -55°C; Polarized: N; SizeAreaWB_mm2: 3; U/M: EA; Value: 0.22uF; TaMax_C: 125°C; SizeZ_mm: 0.6; SizeX_mm: 1; SizeY_mm: 0.5; Cap_Case: 0402; Value2: 16V; CompType: Capacitor; AEC Qualified: Y; Cap_F: 220nF; AEC Category: Q200
C4 = CMP-0006351-2: CAP, CERM, 0.1 uF, 16 V, +/- 10%, X7R, 0402; Manufacturer: MuRata; TaMin_C: -55°C; Polarized: N; SizeAreaWB_mm2: 3; Value1: Unknown; U/M: EA; Value: 0.1uF; TaMax_C: 125°C; SizeZ_mm: 0.6; SizeX_mm: 1; SizeY_mm: 0.5; Cap_Case: 0402; Value2: 16V; CompType: Capacitor; Cap_F: 100nF; AEC Category: Q200
C6 = CMP-0006351-2: CAP, CERM, 0.1 uF, 16 V, +/- 10%, X7R, 0402; Manufacturer: MuRata; TaMin_C: -55°C; Polarized: N; SizeAreaWB_mm2: 3; Value1: Unknown; U/M: EA; Value: 0.1uF; TaMax_C: 125°C; SizeZ_mm: 0.6; SizeX_mm: 1; SizeY_mm: 0.5; Cap_Case: 0402; Value2: 16V; Cap_F: 100nF; AEC Category: Q200
C13 = CMP-0007136-5: CAP, CERM, 1 uF, 16 V, +/- 10%, X7R, AEC-Q200 Grade 1, 0603; Manufacturer: MuRata; TaMin_C: -55°C; Polarized: N; SizeAreaWB_mm2: 4.68; Value1: Unknown; U/M: EA; Value: 1uF; TaMax_C: 125°C; SizeZ_mm: 1; SizeX_mm: 1.6; SizeY_mm: 0.8; Value2: 16V; SizeArea_mm2: 1.28; AEC Qualified: Y; Cap_F: 1µF; AEC Category: Q200
C14 = CMP-0007136-5: CAP, CERM, 1 uF, 16 V, +/- 10%, X7R, AEC-Q200 Grade 1, 0603; Manufacturer: MuRata; TaMin_C: -55°C; Polarized: N; SizeAreaWB_mm2: 4.68; Value1: Unknown; U/M: EA; Value: 1uF; TaMax_C: 125°C; SizeZ_mm: 1; SizeX_mm: 1.6; SizeY_mm: 0.8; Value2: 16V; SizeArea_mm2: 1.28; CompType: Capacitor; AEC Qualified: Y; Cap_F: 1µF; AEC Category: Q200
C17 C45 C52 C58 C65 C83 = CMP-0008017-2: CAP, CERM, 10 uF, 10 V, +/- 10%, X7R, 0805; Manufacturer: MuRata; TaMin_C: -55°C; Polarized: N; SizeAreaWB_mm2: 6.75; Value1: Unknown; U/M: EA; Value: 10uF; TaMax_C: 125°C; SizeZ_mm: 1.45; SizeX_mm: 2; SizeY_mm: 1.25; Cap_Case: 0805; Value2: 10V; SizeArea_mm2: 2.5; CompType: Capacitor; Cap_F: 10µF; AEC Category: Q200
C87 C89 = CMP-0007134-5: CAP, CERM, 2.2 uF, 6.3 V, +/- 10%, X7R, AEC-Q200 Grade 1, 0603; Manufacturer: MuRata; TaMin_C: -55°C; Polarized: N; SizeAreaWB_mm2: 4.68; Value1: Unknown; U/M: EA; Value: 2.2uF; TaMax_C: 125°C; SizeZ_mm: 1; SizeX_mm: 1.6; SizeY_mm: 0.8; Value2: 6.3V; SizeArea_mm2: 1.28; AEC Qualified: Y; Cap_F: 2.2µF; AEC Category: Q200
C101 = CMP-0006352-2: CAP, CERM, 0.01 uF, 25 V, +/- 10%, X7R, 0402; Manufacturer: MuRata; TaMin_C: -55°C; Polarized: N; SizeAreaWB_mm2: 3; Value1: Unknown; U/M: EA; Value: 0.01uF; TaMax_C: 125°C; SizeZ_mm: 0.6; SizeX_mm: 1; SizeY_mm: 0.5; Cap_Case: 0402; Value2: 25V; CompType: Capacitor; Cap_F: 10nF; AEC Category: Q200

## Sheet PROC051B_PWR_In_Reference.SchDoc
size 431 x 279 mm; Date: Not shown in title block; ApprovedBy: Not shown in title block; CheckedBy: Not shown in title block; Author: Not shown in title block; CompanyName: Not shown in title block; Engineer: Not shown in title block; Organization: Not shown in title block; Address1: Not shown in title block; Address2: Not shown in title block; Address3: Not shown in title block; Address4: Not shown in title block; DocumentNumber: 4; Revision: Use project parameter SCH_Rev; SheetNumber: 4; SheetTotal: 16; PageSetup: Record=PageOptions¦CenterHorizontal=True¦CenterVertical=True¦PrintScale=1.00¦XCorrection=1.00¦YCorrection=1.00¦PrintKind=0¦BorderSize=5000000¦LeftOffset=0¦BottomOffset=0¦Orientation=2¦PaperLength=1000¦PaperWidth=1000¦Scale=100¦PaperSource=15¦PrintQuality=600¦MediaType=1¦DitherType=10¦PaperKind=Letter¦PrintScaleMode=1
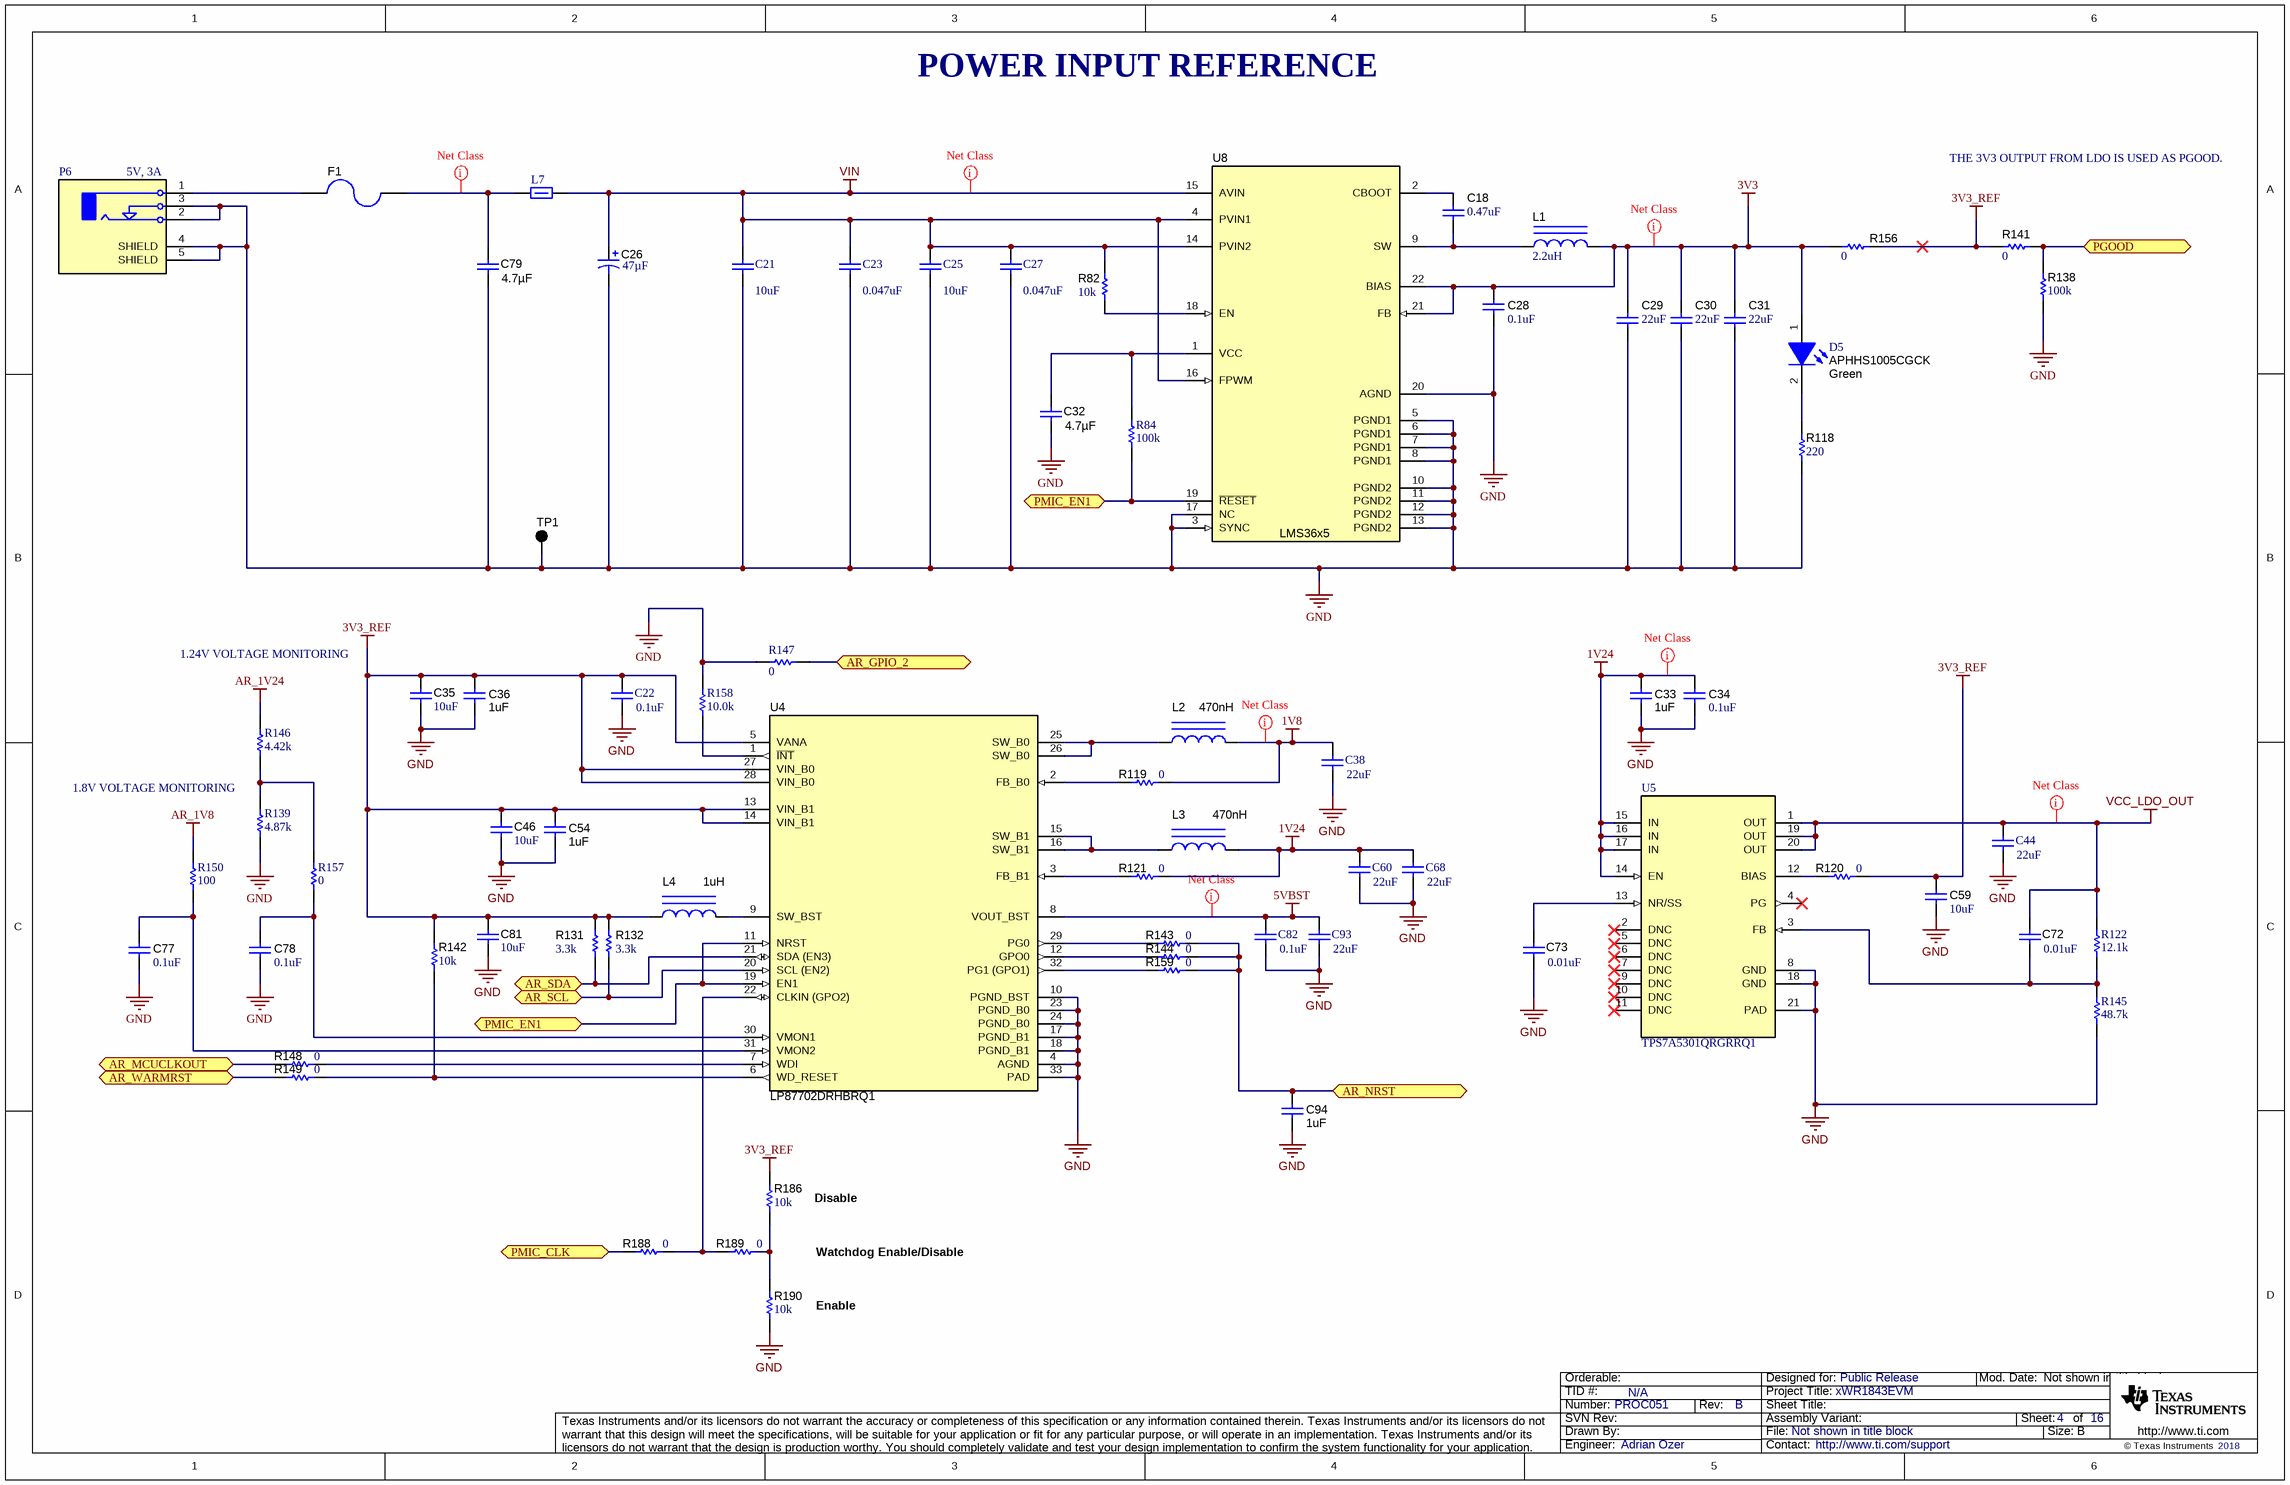
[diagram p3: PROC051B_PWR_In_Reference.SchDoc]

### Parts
C18  ValueDisplayed: 0.47uF  [0402S]  (hidden comment: Capacitor)
C21  ValueDisplayed: 10uF  [1210_280]  (hidden comment: CGA6P1X7R1E106M250AC)
C22  ValueDisplayed: 0.1uF  [0402]  (hidden comment: GCM155R71C104KA55D)
C23  ValueDisplayed: 0.047uF  [0603]  (hidden comment: C1608X7R1H473K080AA)
C25  ValueDisplayed: 10uF  [1210_280]  (hidden comment: CGA6P1X7R1E106M250AC)
C26  ValueDisplayed: 47µF  [3528-21]  (hidden comment: T491B476K010AT)
C27  ValueDisplayed: 0.047uF  [0603]  (hidden comment: C1608X7R1H473K080AA)
C28  ValueDisplayed: 0.1uF  [0402S]  (hidden comment: Capacitor)
C29  ValueDisplayed: 22uF  [1210_280]  (hidden comment: Capacitor)
C30  ValueDisplayed: 22uF  [1210_280]  (hidden comment: Capacitor)
C31  ValueDisplayed: 22uF  [1210_280]  (hidden comment: Capacitor)
C32  ValueDisplayed: 4.7µF  [0805L]  (hidden comment: CGA4J1X7R1E475K125AC)
C33  ValueDisplayed: 1uF  [0603]  (hidden comment: GCM188R71C105KA64D)
C34  ValueDisplayed: 0.1uF  [0402]  (hidden comment: Capacitor)
C35  ValueDisplayed: 10uF  [0805_HV1]  (hidden comment: Capacitor)
C36  ValueDisplayed: 1uF  [0603]  (hidden comment: GCM188R71C105KA64D)
C38  ValueDisplayed: 22uF  [1206_180]  (hidden comment: GCM31CR70J226KE23L)
C44  ValueDisplayed: 22uF  [1206_180]  (hidden comment: GCM31CR70J226KE23L)
C46  ValueDisplayed: 10uF  [0805_HV1]  (hidden comment: Capacitor)
C54  ValueDisplayed: 1uF  [0603]  (hidden comment: GCM188R71C105KA64D)
C59  ValueDisplayed: 10uF  [0805_HV]  (hidden comment: Capacitor)
C60  ValueDisplayed: 22uF  [1206_180]  (hidden comment: GCM31CR70J226KE23L)
C68  ValueDisplayed: 22uF  [1206_180]  (hidden comment: GCM31CR70J226KE23L)
C72  ValueDisplayed: 0.01uF  [0402S]  (hidden comment: Capacitor)
C73  ValueDisplayed: 0.01uF  [0402S]  (hidden comment: Capacitor)
C77  ValueDisplayed: 0.1uF  [0402]  (hidden comment: Capacitor)
C78  ValueDisplayed: 0.1uF  [0402]  (hidden comment: Capacitor)
C79  ValueDisplayed: 4.7µF  [0805L]  (hidden comment: CGA4J1X7R1E475K125AC)
C81  ValueDisplayed: 10uF  [0805_HV1]  (hidden comment: Capacitor)
C82  ValueDisplayed: 0.1uF  [0402]  (hidden comment: 0402YC104KAT2A)
C93  ValueDisplayed: 22uF  [0805_HV]  (hidden comment: GRM21BZ71A226ME15L)
C94  ValueDisplayed: 1uF  [0603]  (hidden comment: GCM188R71C105KA64D)
D5  APHHS1005CGCK  value Green  [APHHS1005_Green]
F1  0440005.WR  [1206]  (value not drawn)
L1  ValueDisplayed: 2.2uH  [XAL5030]  (hidden comment: XAL5030-222MEB)
L2  ValueDisplayed: 470nH  [DFE252012P]  (hidden comment: DFE252012PD-R47M)
L3  ValueDisplayed: 470nH  [DFE252012P]  (hidden comment: DFE252012PD-R47M)
L4  ValueDisplayed: 1uH  [DFE252012P]  (hidden comment: DFE252012PD-1R0M)
L7  HI2220P601R-10  [2220_345]  (value not drawn)
P6  PJ-051AH  [CUI_PJ-051AH]  (value not drawn)
R82  value 10k  [0402L]  (hidden comment: Resistor)
R84  ValueDisplayed: 100k  [0402]  (hidden comment: CRCW0402100KJNED)
R118  ValueDisplayed: 220  [0402]  (hidden comment: CRCW0402220RJNED)
R119  value 0  [0402L]  (hidden comment: Resistor)
R120  value 0  [0402L]  (hidden comment: Resistor)
R121  value 0  [0402L]  (hidden comment: Resistor)
R122  ValueDisplayed: 12.1k  [0402]  (hidden comment: ERA-2AEB1212X)
R131  ValueDisplayed: 3.3k  [0402S]  (hidden comment: Resistor)
R132  ValueDisplayed: 3.3k  [0402S]  (hidden comment: Resistor)
R138  ValueDisplayed: 100k  [0402L]  (hidden comment: CRCW0402100KFKED)
R139  ValueDisplayed: 4.87k  [0402]  (hidden comment: ERA-2AEB4871X)
R141  ValueDisplayed: 0  [0402L]  (hidden comment: ERJ-2GE0R00X)
R142  ValueDisplayed: 10k  [0402]  (hidden comment: CRCW040210K0JNED)
R143  value 0  [0402L]  (hidden comment: Resistor)
R144  value 0  [0402L]  (hidden comment: Resistor)
R145  ValueDisplayed: 48.7k  [0402]  (hidden comment: ERA-2AEB4872X)
R146  ValueDisplayed: 4.42k  [0402]  (hidden comment: ERA-2ARB4421X)
R147  ValueDisplayed: 0  [0402]  (hidden comment: CRCW04020000Z0ED)
R148  value 0  [0402L]  (hidden comment: Resistor)
R149  value 0  [0402L]  (hidden comment: Resistor)
R150  ValueDisplayed: 100  [0402]  (hidden comment: CRCW0402100RFKED)
R156  ValueDisplayed: 0  [2010]  (hidden comment: CRCW20100000Z0EF)
R157  ValueDisplayed: 0  [0402]  (hidden comment: CRCW04020000Z0ED)
R158  ValueDisplayed: 10.0k  [0402]  (hidden comment: CRCW040210K0FKED)
R159  value 0  [0402L]  (hidden comment: Resistor)
R186  ValueDisplayed: 10k  [0402]  (hidden comment: CRCW040210K0JNED)
R188  value 0  [0402L]  (hidden comment: Resistor)
R189  value 0  [0402L]  (hidden comment: Resistor)
R190  ValueDisplayed: 10k  [0402]  (hidden comment: CRCW040210K0JNED)
TP1  5001  [Keystone5001]  (value not drawn)
U4  LP87702DRHBRQ1  [RHB0032N]
U5  TPS7A5301QRGRRQ1  [RGR0020A]
U8  LMS36x5  [RNL0022A_NV]

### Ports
AR_GPIO_2, AR_MCUCLKOUT, AR_NRST, AR_SCL, AR_SDA, AR_WARMRST, PGOOD, PMIC_CLK, PMIC_EN1

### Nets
1V8: C38.1 L2.2 R119.1
1V24: C33.2 C34.1 C60.1 C68.1 L3.2 R121.1 U5.14(EN) U5.15(IN) U5.16(IN) U5.17(IN)
3V3: C28.1 C29.1 C30.1 C31.1 D5.1(A) L1.2 R156.1 U8.21(FB) U8.22(BIAS)
3V3_REF: C22.1 C35.1 C36.2 C46.1 C54.2 C59.1 C81.1 L4.1 R120.1 R131.2 R132.2 R141.1 R142.2 R156.2 R186.2 U4.5(VANA) U4.13(VIN_B1) U4.14(VIN_B1) U4.27(VIN_B0) U4.28(VIN_B0)
5VBST: C82.1 C93.1 U4.8(VOUT_BST)
AR_1V8: R150.2
AR_1V24: R146.2
GND: C21.2 C22.2 C23.2 C25.2 C26.2(-) C27.2 C28.2 C29.2 C30.2 C31.2 C32.2 C33.1 C34.2 C35.2 C36.1 C38.2 C44.2 C46.2 C54.1 C59.2 C60.2 C68.2 C73.2 C77.2 C78.2 C79.2 C81.2 C82.2 C93.2 C94.1 P6.2(TIP) P6.3(TIP_SWITCH) P6.4(SHIELD) P6.5(SHIELD) R118.1 R138.1 R139.1 R145.1 R147.2 R158.2 R190.1 TP1.1 U4.4(AGND) U4.10(PGND_BST) U4.17(PGND_B1) U4.18(PGND_B1) U4.23(PGND_B0) U4.24(PGND_B0) U4.33(PAD) U5.8(GND) U5.18(GND) U5.21(PAD) U8.3(SYNC) U8.5(PGND1) U8.6(PGND1) U8.7(PGND1) U8.8(PGND1) U8.10(PGND2) U8.11(PGND2) U8.12(PGND2) U8.13(PGND2) U8.17(NC) U8.20(AGND)
VCC_LDO_OUT: C44.1 C72.1 R122.2 U5.1(OUT) U5.19(OUT) U5.20(OUT)
VIN: C21.1 C23.1 C25.1 C26.1(+) C27.1 L7.2 R82.1 U8.4(PVIN1) U8.14(PVIN2) U8.15(AVIN) U8.16(FPWM)
AR_GPIO_2: R147.1 ; port AR_GPIO_2
AR_MCUCLKOUT: R148.2 ; port AR_MCUCLKOUT
AR_NRST: C94.2 R143.1 R144.1 R159.1 ; port AR_NRST
AR_SCL: R132.1 U4.20(SCL_(EN2)) ; port AR_SCL
AR_SDA: R131.1 U4.21(SDA_(EN3)) ; port AR_SDA
AR_WARMRST: R149.2 ; port AR_WARMRST
PGOOD: R138.2 R141.2 ; port PGOOD
PMIC_CLK: R188.2 ; port PMIC_CLK
PMIC_EN1: R84.1 U4.11(NRST) U4.19(EN1) U8.19(~{RESET}) ; port PMIC_EN1
NetC18_1: C18.1 U8.2(CBOOT)
NetC18_2: C18.2 L1.1 U8.9(SW)
NetC32_1: C32.1 R84.2 U8.1(VCC)
NetC72_2: C72.2 R122.1 R145.2 U5.3(FB)
NetC73_1: C73.1 U5.13(NR/SS)
NetC77_1: C77.1 R150.1 U4.31(VMON2)
NetC78_1: C78.1 R157.1 U4.30(VMON1)
NetC79_1: C79.1 F1.1 L7.1
NetD5_2: D5.2(K) R118.2
NetF1_2: F1.2 P6.1(SLEEVE)
NetL2_1: L2.1 U4.25(SW_B0) U4.26(SW_B0)
NetL3_1: L3.1 U4.15(SW_B1) U4.16(SW_B1)
NetL4_2: L4.2 U4.9(SW_BST)
NetR82_2: R82.2 U8.18(EN)
NetR119_2: R119.2 U4.2(FB_B0)
NetR120_2: R120.2 U5.12(BIAS)
NetR121_2: R121.2 U4.3(FB_B1)
NetR139_2: R139.2 R146.1 R157.2
NetR142_1: R142.1 R149.1 U4.6(WD_RESET)
NetR143_2: R143.2 U4.29(PG0)
NetR144_2: R144.2 U4.12(GPO0)
NetR148_1: R148.1 U4.7(WDI)
NetR158_1: R158.1 U4.1(~{INT})
NetR159_2: R159.2 U4.32(PG1_(GPO1))
NetR186_1: R186.1 R189.1 R190.2
NetR188_1: R188.1 R189.2 U4.22(CLKIN_(GPO2))

Not connected (* = marked no-connect by the designer): U5 2(DNC)* 4(PG)* 5(DNC)* 6(DNC)* 7(DNC)* 9(DNC)* 10(DNC)* 11(DNC)*

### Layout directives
net class Undefined: VCC_LDO_OUT
net class PWR: 1V8, 1V24, 3V3, 5VBST, NetC79_1, VIN

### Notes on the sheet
- POWER INPUT REFERENCE
- THE 3V3 OUTPUT FROM LDO IS USED AS PGOOD.
- (near P6) 5V, 3A
- 1.24V VOLTAGE MONITORING
- 1.8V VOLTAGE MONITORING
- (near R186) Disable
- (near R190) Enable
- Watchdog Enable/Disable

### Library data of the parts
C18 = CMP-0006717-2: CAP, CERM, 0.47 uF, 6.3 V, +/- 10%, X7R, 0402; PartNumber: JMK105B7474KVHF; Manufacturer: Taiyo Yuden; Polarized: N; Value: 0.47uF; U/M: EA; Cap_F: 470nF; Value1: Unknown; VDC_V: 6.3V; TaMin_C: -55°C; TaMax_C: 125°C; Cap_Case: 0402; SizeArea_mm2: 0.5; SizeAreaWB_mm2: 3; SizeX_mm: 1; SizeZ_mm: 0.6; AEC Category: Q200
C21 C25 = CMP-0009155-2: CAP, CERM, 10 uF, 25 V, +/- 20%, X7R, AEC-Q200 Grade 1, 1210; Manufacturer: TDK; TaMin_C: -55°C; Polarized: N; SizeAreaWB_mm2: 14.7; Value1: Unknown; U/M: EA; Value: 10uF; TaMax_C: 125°C; SizeZ_mm: 2.8; SizeX_mm: 3.2; SizeY_mm: 2.5; Cap_Case: 1210; Value2: 25V; SizeArea_mm2: 8; AEC Qualified: Y; Cap_F: 10µF; AEC Grade: 1; AEC Category: Q200
C22 = CMP-0006351-2: CAP, CERM, 0.1 uF, 16 V, +/- 10%, X7R, 0402; Manufacturer: MuRata; TaMin_C: -55°C; Polarized: N; SizeAreaWB_mm2: 3; Value1: Unknown; U/M: EA; Value: 0.1uF; TaMax_C: 125°C; SizeZ_mm: 0.6; SizeX_mm: 1; SizeY_mm: 0.5; Value2: 16V; Cap_F: 100nF; AEC Category: Q200
C23 C27 = CMP-0007049-4: CAP, CERM, 0.047 uF, 50 V, +/- 10%, X7R, 0603; Manufacturer: TDK; TaMin_C: -55°C; ESR_ohm: 0.049007; Polarized: N; SizeAreaWB_mm2: 4.68; Value1: 0.049007 ohm; U/M: EA; TaMax_C: 125°C; SizeZ_mm: 1; SizeX_mm: 1.6; SizeY_mm: 0.8; Value2: 50V; SizeArea_mm2: 1.28; Cap_F: 47nF; IRMS_A: 7.67528dA; AEC Category: Q200
C26 = CMP-0078216-1: CAP, TA, 47 µF, 10 V, +/- 10%, SMD; Manufacturer: Kemet; TaMin_C: -55°C; Polarized: Y; SizeAreaWB_mm2: 17.1; Value: 47uF; TaMax_C: 125°C; SizeZ_mm: 2.1; SizeX_mm: 3.5; SizeY_mm: 2.8; Value2: 10V; SizeArea_mm2: 9.8; CompType: Capacitor; AEC Qualified: N; AEC Category: Q200
C28 = CMP-0006201-2: CAP, CERM, 0.1 uF, 16 V, +/- 10%, X7R, 0402; PartNumber: 0402YC104KAT2A; Manufacturer: AVX; Polarized: N; Value: 0.1uF; U/M: EA; Cap_F: 100nF; Value1: Unknown; VDC_V: 16V; TaMin_C: -55°C; TaMax_C: 125°C; Cap_Case: 0402; SizeArea_mm2: 0.5; SizeAreaWB_mm2: 3; SizeX_mm: 1; SizeZ_mm: 0.6; AEC Category: Q200
C29-C31 = CMP-0009116-1: CAP, CERM, 22 uF, 16 V, +/- 10%, X7R, 1210; PartNumber: C3225X7R1C226K250AC; Manufacturer: TDK; Polarized: N; Value: 22uF; U/M: EA; Cap_F: 22µF; ESR_ohm: 2.582m; Value1: 0.002582 ohm; VDC_V: 16V; IRMS_A: 4.57562A; TaMin_C: -55°C; TaMax_C: 125°C; SizeArea_mm2: 8; SizeAreaWB_mm2: 14.7; SizeX_mm: 3.2; SizeY_mm: 2.5; SizeZ_mm: 2.8; AEC Category: Q200
C32 C79 = CMP-0076706-1: CAP, CERM, 4.7 µF, 25 V,+/- 10%, X7R, AEC-Q200 Grade 1, 0805; Manufacturer: TDK; SizeAreaWB_mm2: 6.75; SizeArea_mm2: 2.5; AEC Qualified: Y; AEC Category: Q200; Value: 4.7uF; TaMax_C: 125°C; SizeZ_mm: 1.45; AEC Grade: 1; Polarized: N; TaMin_C: -55°C; VDC_V: 25V; SizeY_mm: 1.25; U/M: EA; CompType: Capacitor; SizeX_mm: 2.0; Cap_Case: 2x1.25x1.25mm
C33 C36 C54 C94 = CMP-0007136-5: as C13 on sheet PROC051B_Decoupling_Caps_Reference
C34 C77 C78 = CMP-0006201-2: CAP, CERM, 0.1 uF, 16 V, +/- 10%, X7R, 0402; PartNumber: 0402YC104KAT2A; Manufacturer: AVX; Polarized: N; Value: 0.1uF; U/M: EA; Cap_F: 100nF; Value1: Unknown; VDC_V: 16V; TaMin_C: -55°C; TaMax_C: 125°C; SizeArea_mm2: 0.5; SizeAreaWB_mm2: 3; SizeX_mm: 1; SizeZ_mm: 0.6; AEC Category: Q200
C35 C46 C81 = CMP-0007995-2: CAP, CERM, 10 uF, 16 V, +/- 10%, X7R, 0805; PartNumber: CL21B106KOQNNNE; Manufacturer: Samsung Electro-Mechanics; Polarized: N; Value: 10uF; U/M: EA; Cap_F: 10µF; Value1: Unknown; VDC_V: 16V; TaMin_C: -55°C; TaMax_C: 125°C; Cap_Case: 0805; SizeArea_mm2: 2.5; SizeAreaWB_mm2: 6.75; SizeX_mm: 2; SizeY_mm: 1.25; SizeZ_mm: 1.45; AEC Category: Q200
C38 C44 C60 C68 = CMP-0008809-2: CAP, CERM, 22 uF, 6.3 V, +/- 10%, X7R, AEC-Q200 Grade 1, 1206; Manufacturer: MuRata; TaMin_C: -55°C; Polarized: N; SizeAreaWB_mm2: 10.92; Value1: Unknown; U/M: EA; Value: 22uF; TaMax_C: 125°C; SizeZ_mm: 1.8; SizeX_mm: 3.2; SizeY_mm: 1.6; Cap_Case: 1206; Value2: 6.3V; SizeArea_mm2: 5.12; AEC Qualified: Y; Cap_F: 22µF; AEC Grade: 1; AEC Category: Q200
C59 = CMP-0008017-2: CAP, CERM, 10 uF, 10 V, +/- 10%, X7R, 0805; PartNumber: GCM21BR71A106KE22L; Manufacturer: MuRata; Polarized: N; Value: 10uF; U/M: EA; Cap_F: 10µF; Value1: Unknown; VDC_V: 10V; TaMin_C: -55°C; TaMax_C: 125°C; Cap_Case: 0805; SizeArea_mm2: 2.5; SizeAreaWB_mm2: 6.75; SizeX_mm: 2; SizeY_mm: 1.25; SizeZ_mm: 1.45; AEC Category: Q200
C72 C73 = CMP-0006639-2: CAP, CERM, 0.01 uF, 16 V, +/- 10%, X7R, 0402; PartNumber: GRM155R71C103KA01D; Manufacturer: MuRata; Polarized: N; Value: 0.01uF; U/M: EA; Cap_F: 10nF; Value1: Unknown; VDC_V: 16V; TaMin_C: -55°C; TaMax_C: 125°C; Cap_Case: 0402; AEC Category: Q200; SizeArea_mm2: 0.5; SizeAreaWB_mm2: 3; SizeX_mm: 1; SizeZ_mm: 0.6
C82 = CMP-0006201-2: CAP, CERM, 0.1 uF, 16 V, +/- 10%, X7R, 0402; Manufacturer: AVX; TaMin_C: -55°C; Polarized: N; SizeAreaWB_mm2: 3; Value1: Unknown; U/M: EA; Value: 0.1uF; TaMax_C: 125°C; SizeZ_mm: 0.6; SizeX_mm: 1; SizeY_mm: 0.5; Value2: 16V; Cap_F: 100nF; AEC Category: Q200
C93 = CMP-0008377-2: CAP, CERM, 22 uF, 10 V, +/- 20%, X7R, 0805; Manufacturer: MuRata; SizeY_mm: 1.25; Cap_Case: 0805; Value2: 10V; SizeArea_mm2: 2.5; CompType: Capacitor; AEC Qualified: N; Cap_F: 22µF; AEC Category: Q200; TaMin_C: -55°C; SizeAreaWB_mm2: 6.75; Value1: Unknown; U/M: EA; Value: 22uF; TaMax_C: 125°C; SizeZ_mm: 1.45; SizeX_mm: 2
D5 = CMP-0067682-2: LED, Green, SMD; Manufacturer: Kingbright; Io_A: 20mA; Power_TotalModule: 75mW; SizeAreaWB_mm2: 3.0; Vr_V: 5V; Tjmax_C: 85°C; Value1: 0.075W; Angle: 120.0; SizeZ_mm: 0.6; SizeX_mm: 1.0; SizeY_mm: 0.5; Ir_A: 10µA; Vf_V: 2.1V
F1 = CMP-0003458-2: Fuse, 5 A, 32VAC/VDC, SMD; Manufacturer: Littelfuse; Irating_A: 5A; SizeAreaWB_mm2: 10.92; Interrupt_AC: 50A; VAC_V: 32V; SizeZ_mm: 1.35; SizeX_mm: 3.2; SizeY_mm: 1.6; SizeArea_mm2: 5.12; Rtyp_Ohm: 0.012; MeltingTyp: 4.761
L1 = CMP-0061001-2: Inductor, Shielded, Composite, 2.2 µH, 9.2 A, 0.01 ohm, AEC-Q200 Grade 1, SMD; Manufacturer: Coilcraft; Isat: 12.9A @ 30% inductance drop; Irms: 9.2A @ 40C rise; Green_Lifecycle: Not Set; SizeAreaWB_mm2: 54.4544; DCR_ohm: 0.01; Green_REACh: Incomplete; Value: 2.2uH; Imax_A: 9.2A; SizeZ_mm: 3.1; SizeX_mm: 5.28; SizeY_mm: 5.48; SizeArea_mm2: 28.9344; Ind_H: 2.2µH; AEC Qualified: 1; AEC Category: Q200; AEC Grade: Y
L2 L3 = CMP-0058944-1: Inductor, Shielded, 470 nH, 4.7 A, 0.021 ohm, SMD; Manufacturer: MuRata Toko; Isat: 6.1A @ 30% inductance drop; Irms: 4.7A @ 40C rise; SizeAreaWB_mm2: 10.5; DCR_ohm: 0.021; Value: 470nH; Imax_A: 4.7A; SizeZ_mm: 1.2; SizeX_mm: 2.5; SizeY_mm: 2; SizeArea_mm2: 5; AEC Category: Q200
L4 = CMP-0058938-1: Inductor, Shielded, 1 uH, 3.8 A, 0.035 ohm, AEC-Q200 Grade 1, SMD; Manufacturer: MuRata Toko; Isat: 4.5A @ 30% inductance drop; Irms: 3.8A @ 40C rise; SizeAreaWB_mm2: 10.5; DCR_ohm: 0.035; Value: 1uH; Imax_A: 3.8A; SizeZ_mm: 1.2; SizeX_mm: 2.5; SizeY_mm: 2; SizeArea_mm2: 5; Ind_H: 1µH; AEC Qualified: Y; AEC Grade: 1; AEC Category: Q200
L7 = CMP-0003388-1: Ferrite Bead, 600 ohm @ 100 MHz, 4 A, 2220; Manufacturer: Laird-Signal Integrity Products; Ztyp@1GHz_Ohm: 106; ZTyp@100MHz_Ohm: 600; SizeAreaWB_mm2: 53.96; DCR_ohm: 0.025; Value1: 0.025 ohm; Value: 600 ohm; Imax_A: 4A; SizeZ_mm: 3.45; SizeX_mm: 5.6; SizeY_mm: 5.1; SizeArea_mm2: 28.56
P6 = CMP-0081851-1: DC Power Jack, R/A, TH; Manufacturer: CUI Inc.; Gender: Male; Cert_UL: Y; Current_A: 5A; Voltage_V: 24V
R82 = CMP-0026825-5: RES, 10 k, 5%, 0.063 W, AEC-Q200 Grade 0, 0402; PartNumber: CRCW040210K0JNED; Manufacturer: Vishay-Dale; Value_Code: 10k0; Power_W: 63mW; Value2: 0.063W; VDC_V: 50V; TempCo: 200 ppm/C; EIA_Code: E24; AEC Category: Q200; AEC Grade: 0; AEC Qualified: Y; SizeArea_mm2: 0.5; SizeX_mm: 1; SizeZ_mm: 0.6
R84 = CMP-0026823-3: RES, 100 k, 5%, 0.063 W, AEC-Q200 Grade 0, 0402; Manufacturer: Vishay-Dale; Power_W: 63mW; TempCo: 200 ppm/C; Value: 100k; EIA_Code: E24; SizeX_mm: 1; SizeY_mm: 0.5; SizeZ_mm: 0.6; Value2: 0.063W; AEC Qualified: Y; VDC_V: 50V; AEC Category: Q200; AEC Grade: 0
R118 = CMP-0026878-3: RES, 220, 5%, 0.063 W, AEC-Q200 Grade 0, 0402; Manufacturer: Vishay-Dale; Power_W: 63mW; TempCo: 200 ppm/C; Value_Code: 220R; Value: 220; EIA_Code: E24; SizeX_mm: 1; SizeY_mm: 0.5; SizeZ_mm: 0.6; Value2: 0.063W; AEC Qualified: Y; VDC_V: 50V; AEC Category: Q200; AEC Grade: 0
R119-R121 R143 R144 R148 R149 R159 R188 R189 = CMP-0026822-3: as R47 on sheet PROC051B_DUT_Reference
R122 = CMP-0083631-1: RES, 12.1 k, 0.1%, 0.063 W, AEC-Q200 Grade 0, 0402; Manufacturer: Panasonic; Power_W: 63mW; TempCo: 25 ppm/C; SizeAreaWB_mm2: 3; Value_Code: 12k1; Value: 12.1k; EIA_Code: E192; SizeX_mm: 1; SizeY_mm: 0.5; SizeZ_mm: 0.6; Value2: 0.063W; CompType: Resistor; AEC Qualified: Y; VDC_V: 50V; AEC Grade: 0; AEC Category: Q200
R131 R132 = CMP-0026918-5: RES, 3.3 k, 5%, 0.063 W, AEC-Q200 Grade 0, 0402; PartNumber: CRCW04023K30JNED; Manufacturer: Vishay-Dale; Value: 3.3k; Value_Code: 3k30; Power_W: 63mW; Value2: 0.063W; VDC_V: 50V; TempCo: 200 ppm/C; SizeArea_mm2: 0.5; SizeX_mm: 1; SizeZ_mm: 0.6; EIA_Code: E24; AEC Category: Q200; AEC Qualified: Y; AEC Grade: 0
R138 = CMP-0025950-3: RES, 100 k, 1%, 0.063 W, AEC-Q200 Grade 0, 0402; Manufacturer: Vishay-Dale; Power_W: 63mW; TempCo: 100 ppm/C; Value: 100k; EIA_Code: E96; SizeX_mm: 1; SizeY_mm: 0.5; SizeZ_mm: 0.6; Value2: 0.063W; AEC Qualified: Y; VDC_V: 50V; AEC Category: Q200; AEC Grade: 0
R139 = CMP-0026781-1: RES, 4.87 k, 0.1%, 0.062 W, AEC-Q200 Grade 0, 0402; Manufacturer: Panasonic; Power_W: 62mW; TempCo: 25 ppm/C; Value_Code: 4k87; U/M: EA; Value: 4.87k; EIA_Code: E192; SizeX_mm: 1; SizeY_mm: 0.5; SizeZ_mm: 0.6; Value2: 0.062W; AEC Qualified: Y; VDC_V: 25V; AEC Grade: 0; AEC Category: Q200
R141 = CMP-0026992-3: RES, 0, 5%, 0.1 W, AEC-Q200 Grade 0, 0402; Manufacturer: Panasonic; Power_W: 100mW; TempCo: 600 ppm/C; Value_Code: 0000; Value: 0; EIA_Code: E24; SizeX_mm: 1; SizeY_mm: 0.5; SizeZ_mm: 0.6; Value2: 0.1W; AEC Qualified: Y; VDC_V: 50V; AEC Category: Q200; SizeAreaWB_mm2: 3
R142 R186 R190 = CMP-0026825-5: RES, 10 k, 5%, 0.063 W, AEC-Q200 Grade 0, 0402; Manufacturer: Vishay-Dale; Power_W: 63mW; TempCo: 200 ppm/C; Value_Code: 10k0; Value: 10k; EIA_Code: E24; SizeX_mm: 1; SizeY_mm: 0.5; SizeZ_mm: 0.6; Value2: 0.063W; AEC Qualified: Y; VDC_V: 50V; AEC Category: Q200; AEC Grade: 0
R145 = CMP-0083632-1: RES, 48.7 k, 0.1%, 0.063 W, AEC-Q200 Grade 0, 0402; Manufacturer: Panasonic; Power_W: 63mW; TempCo: 25 ppm/C; SizeAreaWB_mm2: 3; Value_Code: 48k7; Value: 48.7k; EIA_Code: E192; SizeX_mm: 1; SizeY_mm: 0.5; SizeZ_mm: 0.6; Value2: 0.063W; AEC Qualified: Y; VDC_V: 50V; AEC Grade: 0; AEC Category: Q200
R146 = CMP-0083657-1: RES, 4.42 k, 0.1%, 0.063 W, AEC-Q200 Grade 0, 0402; Manufacturer: Panasonic; Value_Code: 4k42; SizeAreaWB_mm2: 3; SizeArea_mm2: 0.5; AEC Qualified: Y; AEC Category: Q200; Value: 4.42k; SizeZ_mm: 0.6; EIA_Code: E192; TempCo: 10 ppm/C; AEC Grade: 0; Power_W: 63mW; Value2: 0.063W; SizeX_mm: 1
R147 = CMP-0026822-3: RES, 0, 5%, 0.063 W, AEC-Q200 Grade 0, 0402; Manufacturer: Vishay-Dale; Power_W: 63mW; TempCo: 200 ppm/C; Value_Code: 0000; Value: 0; EIA_Code: E24; SizeX_mm: 1; SizeY_mm: 0.5; SizeZ_mm: 0.6; Value2: 0.063W; AEC Qualified: Y; VDC_V: 50V; AEC Category: Q200
R150 = CMP-0025951-3: RES, 100, 1%, 0.063 W, AEC-Q200 Grade 0, 0402; Manufacturer: Vishay-Dale; Power_W: 63mW; TempCo: 100 ppm/C; Value_Code: 100R; Value: 100; EIA_Code: E96; SizeX_mm: 1; SizeY_mm: 0.5; SizeZ_mm: 0.6; Value2: 0.063W; AEC Qualified: Y; VDC_V: 50V; AEC Category: Q200; AEC Grade: 0
R156 = CMP-0016044-3: RES, 0, 5%, 0.75 W, AEC-Q200 Grade 0, 2010; Manufacturer: Vishay-Dale; Power_W: 750mW; TempCo: ppm/C; Value_Code: 0000; Value: 0; EIA_Code: E24; SizeX_mm: 5; SizeY_mm: 2.5; SizeZ_mm: 1.66; Value2: 0.75W; SizeArea_mm2: 12.5; CompType: Resistor; AEC Qualified: Y; AEC Category: Q200
R157 = CMP-0026822-3: as R46 on sheet PROC051B_DUT_Reference
R158 = CMP-0025958-3: as R13 on sheet PROC051B_DUT_Reference
TP1 = CMP-0055138-1: Test Point, Miniature, Black, TH; Manufacturer: Keystone; CNHeader: FALSE; Green_Lifecycle: Active; Green_REACh: Passed; ContactFinish: Silver; CT: TRUE
U4 = CMP-0078631-1: Boost and Dual Buck Regulators With Diagnostic Functions, RHB0032N (VQFN-32); Manufacturer: Texas Instruments; SizeArea_mm2: 25; SizeAreaWB_mm2: 49; SizeX_mm: 5; SizeZ_mm: 0.9; CompType: IC; AEC Category: Q200; AEC Qualified: Y
U5 = CMP-0077268-2: Automotive 3A High-Accuracy Low-Noise Low-Dropout (LDO) Voltage Regulator, RGR0020A (VQFN-20); Manufacturer: Texas Instruments; SizeAreaWB_mm2: 20.25; SizeZ_mm: 1.0; SizeX_mm: 3.5; SizeArea_mm2: 12.25; CompType: IC; AEC Qualified: Y; AEC Category: Q200
U8 = CMP-0076346-4: 2.5A, 36 V Synchronous, 2.1MHz, Automotive Step Down DC-DC Converter, RNL0022A (VQFN-HR-22); PartNumber: LM536253QRNLRQ1; Alternate PartNumber: LM536253QRNLTQ1; Manufacturer: Texas Instruments; SizeArea_mm2: 20.0; SizeAreaWB_mm2: 42.0; SizeX_mm: 4.0; SizeY_mm: 5.0; SizeZ_mm: 0.9; CompType: IC; AEC Category: Q200; AEC Qualified: Y

## Sheet PROC051B_LC_Filtering_Reference.SchDoc
size 431 x 279 mm; Date: Not shown in title block; ApprovedBy: Not shown in title block; CheckedBy: Not shown in title block; Author: Not shown in title block; CompanyName: Not shown in title block; Engineer: Not shown in title block; Organization: Not shown in title block; Address1: Not shown in title block; Address2: Not shown in title block; Address3: Not shown in title block; Address4: Not shown in title block; DocumentNumber: 5; Revision: Use project parameter SCH_Rev; SheetNumber: 5; SheetTotal: 16; PageSetup: Record=PageOptions¦CenterHorizontal=True¦CenterVertical=True¦PrintScale=1.00¦XCorrection=1.00¦YCorrection=1.00¦PrintKind=0¦BorderSize=5000000¦LeftOffset=0¦BottomOffset=0¦Orientation=2¦PaperLength=1000¦PaperWidth=1000¦Scale=100¦PaperSource=15¦PrintQuality=600¦MediaType=1¦DitherType=10¦PaperKind=Letter¦PrintScaleMode=1
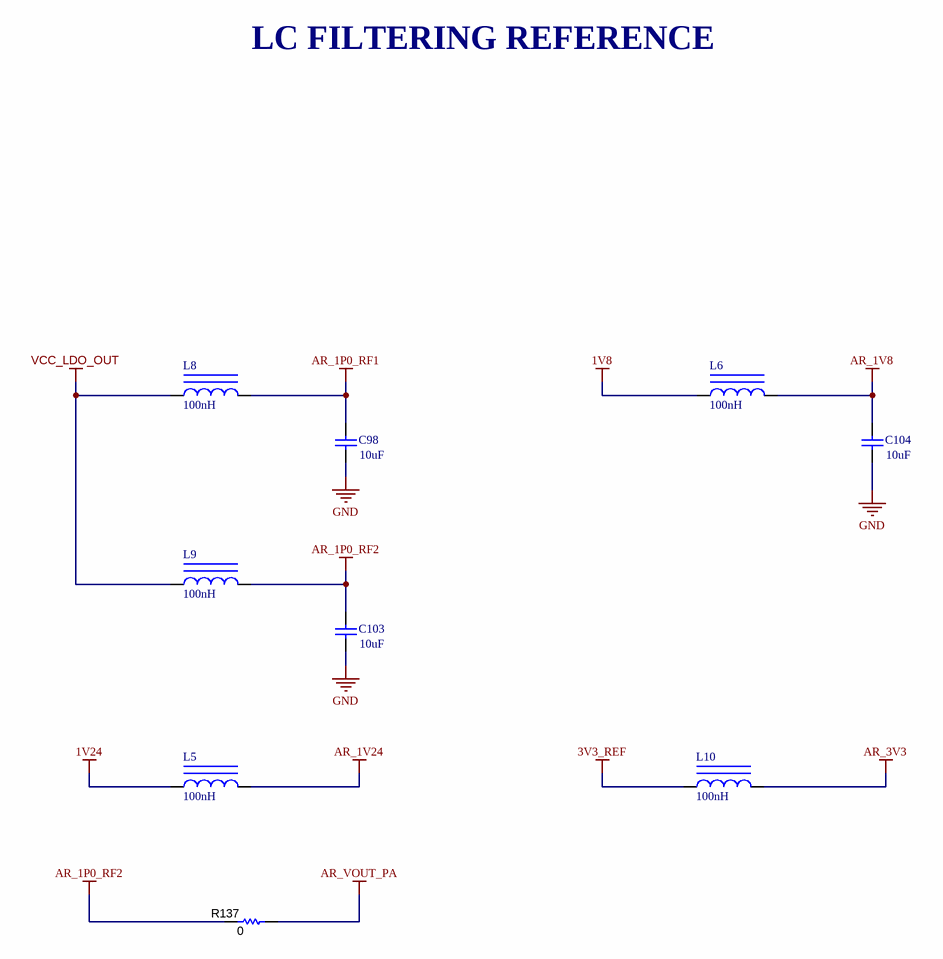
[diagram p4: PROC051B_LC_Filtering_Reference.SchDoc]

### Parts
C98  ValueDisplayed: 10uF  [0805_HV]  (hidden comment: GCM21BR71A106KE22L)
C103  ValueDisplayed: 10uF  [0805_HV]  (hidden comment: GCM21BR71A106KE22L)
C104  ValueDisplayed: 10uF  [0805_HV]  (hidden comment: GCM21BR71A106KE22L)
L5  ValueDisplayed: 100nH  [NLCV32]  (hidden comment: NLCV32T-R10M-EFRD)
L6  ValueDisplayed: 100nH  [NLCV32]  (hidden comment: NLCV32T-R10M-EFRD)
L8  ValueDisplayed: 100nH  [NLCV32]  (hidden comment: NLCV32T-R10M-EFRD)
L9  ValueDisplayed: 100nH  [NLCV32]  (hidden comment: NLCV32T-R10M-EFRD)
L10  ValueDisplayed: 100nH  [NLCV32]  (hidden comment: NLCV32T-R10M-EFRD)
R137  ValueDisplayed: 0  [0603]  (hidden comment: MCT06030Z0000ZP500)

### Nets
1V8: L6.1
1V24: L5.1
3V3_REF: L10.1
AR_1P0_RF1: C98.1 L8.2
AR_1P0_RF2: C103.1 L9.2 R137.1
AR_1V8: C104.1 L6.2
AR_1V24: L5.2
AR_3V3: L10.2
AR_VOUT_PA: R137.2
GND: C98.2 C103.2 C104.2
VCC_LDO_OUT: L8.1 L9.1

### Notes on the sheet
- LC FILTERING REFERENCE

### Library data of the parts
C98 C103 C104 = CMP-0008017-2: CAP, CERM, 10 uF, 10 V, +/- 10%, X7R, 0805; Manufacturer: MuRata; TaMin_C: -55°C; Polarized: N; SizeAreaWB_mm2: 6.75; Value1: Unknown; U/M: EA; Value: 10uF; TaMax_C: 125°C; SizeZ_mm: 1.45; SizeX_mm: 2; SizeY_mm: 1.25; Cap_Case: 0805; Value2: 10V; SizeArea_mm2: 2.5; Cap_F: 10µF; AEC Category: Q200
L5 L6 L8-L10 = CMP-0083745-1: Inductor, Wirewound, Ferrite, 100 nH, 2.85 A, 0.024 ohm, AEC-Q200 Grade 1, SMD; Manufacturer: TDK; Isat: 2.85A @ 10% inductance drop; Irms: 2.85A @ 40C rise; SizeAreaWB_mm2: 13.44; DCR_ohm: 0.024; Value: 100nH; Imax_A: 2.85A; SizeZ_mm: 2.5; SizeX_mm: 3.2; SizeY_mm: 2.2; SizeArea_mm2: 7.04; AEC Qualified: Y; AEC Grade: 1; AEC Category: Q200
R137 = CMP-0025884-3: RES, 0, 5%, 0.125 W, 0603; Manufacturer: Vishay/Beyschlag; Power_W: 125mW; TempCo: ppm/C; Value_Code: 0000; U/M: EA; Value: 0; EIA_Code: E24; SizeX_mm: 1.6; SizeY_mm: 0.8; SizeZ_mm: 1; Value2: 0.125W; SizeArea_mm2: 1.28; CompType: Resistor; AEC Qualified: N; AEC Category: Q200

## Sheet PROC051B_QSPI_Flash_Reference.SchDoc: QSPI flash section
size 431 x 279 mm; Date: Not shown in title block; ApprovedBy: Not shown in title block; CheckedBy: Not shown in title block; Author: Not shown in title block; CompanyName: Not shown in title block; Engineer: Not shown in title block; Organization: Not shown in title block; Address1: Not shown in title block; Address2: Not shown in title block; Address3: Not shown in title block; Address4: Not shown in title block; DocumentNumber: 6; Revision: Use project parameter SCH_Rev; SheetNumber: 6; SheetTotal: 16; PageSetup: Record=PageOptions¦CenterHorizontal=True¦CenterVertical=True¦PrintScale=1.00¦XCorrection=1.00¦YCorrection=1.00¦PrintKind=0¦BorderSize=5000000¦LeftOffset=0¦BottomOffset=0¦Orientation=2¦PaperLength=1000¦PaperWidth=1000¦Scale=100¦PaperSource=15¦PrintQuality=600¦MediaType=1¦DitherType=10¦PaperKind=Letter¦PrintScaleMode=1
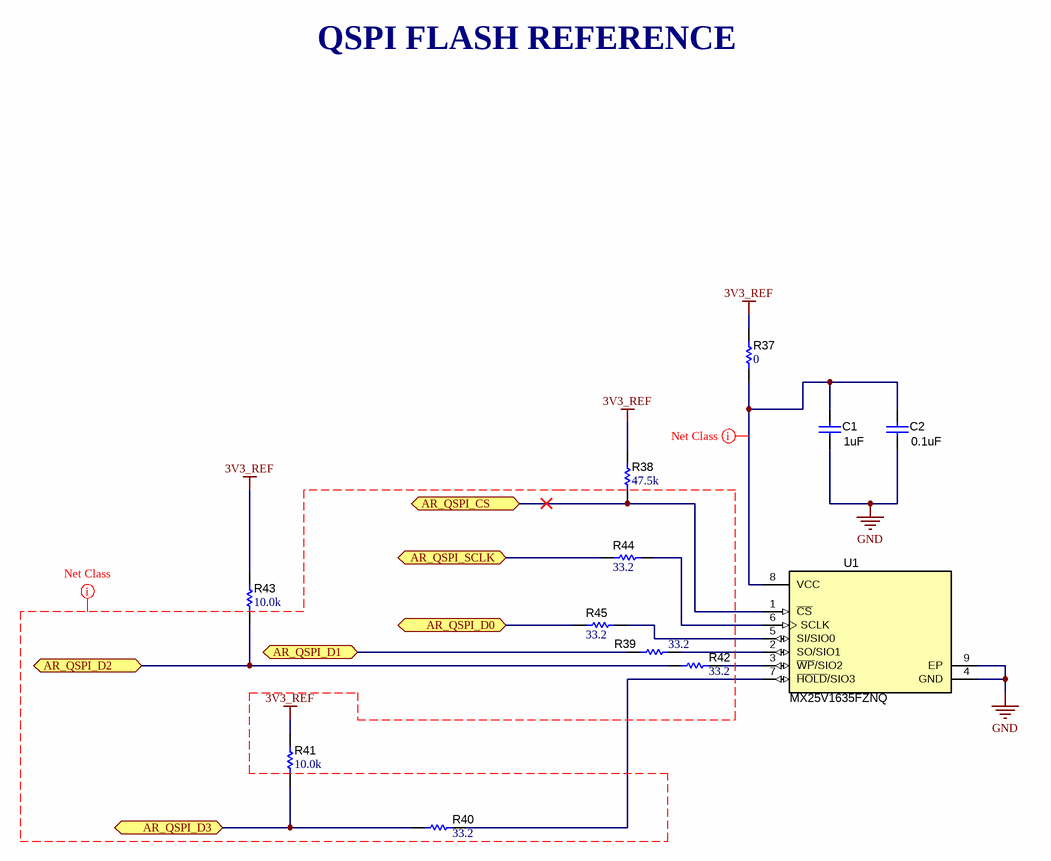
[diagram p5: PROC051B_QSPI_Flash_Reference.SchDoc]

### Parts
C1  ValueDisplayed: 1uF  [0603]  (hidden comment: GCM188R71C105KA64D)
C2  ValueDisplayed: 0.1uF  [0402L]  (hidden comment: CGA2B3X7R1H104K050BB)
R37  ValueDisplayed: 0  [0402L]  (hidden comment: ERJ-2GE0R00X)
R38  ValueDisplayed: 47.5k  [0402L]  (hidden comment: CRCW040247K5FKED)
R39  ValueDisplayed: 33.2  [0201_Silk]  (hidden comment: CRCW020133R2FNED)
R40  ValueDisplayed: 33.2  [0201_Silk]  (hidden comment: CRCW020133R2FNED)
R41  ValueDisplayed: 10.0k  [0402L]  (hidden comment: CRCW040210K0FKED)
R42  ValueDisplayed: 33.2  [0201_Silk]  (hidden comment: CRCW020133R2FNED)
R43  ValueDisplayed: 10.0k  [0402L]  (hidden comment: CRCW040210K0FKED)
R44  ValueDisplayed: 33.2  [0201_Silk]  (hidden comment: CRCW020133R2FNED)
R45  ValueDisplayed: 33.2  [0201_Silk]  (hidden comment: CRCW020133R2FNED)
U1  MX25V1635FZNQ  [WSON-8L_6x5MM_EP]

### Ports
AR_QSPI_CS, AR_QSPI_D0, AR_QSPI_D1, AR_QSPI_D2, AR_QSPI_D3, AR_QSPI_SCLK

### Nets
3V3_REF: R37.1 R38.2 R41.2 R43.2
GND: C1.1 C2.1 U1.4(GND) U1.9(EP)
AR_QSPI_CS: R38.1 U1.1(~{CS}) ; port AR_QSPI_CS
AR_QSPI_D0: R45.2 ; port AR_QSPI_D0
AR_QSPI_D1: R39.1 ; port AR_QSPI_D1
AR_QSPI_D2: R42.1 R43.1 ; port AR_QSPI_D2
AR_QSPI_D3: R40.2 R41.1 ; port AR_QSPI_D3
AR_QSPI_SCLK: R44.2 ; port AR_QSPI_SCLK
NetC1_2: C1.2 C2.2 R37.2 U1.8(VCC)
NetR39_2: R39.2 U1.2(SO/SIO1)
NetR40_1: R40.1 U1.7(~{HOLD}/SIO3)
NetR42_2: R42.2 U1.3(~{WP}/SIO2)
NetR44_1: R44.1 U1.6(SCLK)
NetR45_1: R45.1 U1.5(SI/SIO0)

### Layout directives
net class PWR: NetC1_2
net class QSPI: 3V3_REF

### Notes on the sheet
- QSPI FLASH REFERENCE

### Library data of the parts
C1 = CMP-0007136-5: as C13 on sheet PROC051B_Decoupling_Caps_Reference
C2 = CMP-0006325-2: CAP, CERM, 0.1 uF, 50 V, +/- 10%, X7R, AEC-Q200 Grade 1, 0402; Manufacturer: TDK; TaMin_C: -55°C; ESR_ohm: 0.039064; Polarized: N; SizeAreaWB_mm2: 3; Value1: 0.039064 ohm; U/M: EA; Value: 0.1uF; TaMax_C: 125°C; SizeZ_mm: 0.6; SizeX_mm: 1; SizeY_mm: 0.5; Cap_Case: 0402; Value2: 50V; AEC Qualified: Y; Cap_F: 100nF; IRMS_A: 8.14669dA; AEC Category: Q200
R37 = CMP-0026992-3: as R141 on sheet PROC051B_PWR_In_Reference
R38 = CMP-0026395-2: RES, 47.5 k, 1%, 0.063 W, AEC-Q200 Grade 0, 0402; Manufacturer: Vishay-Dale; Power_W: 63mW; TempCo: 100 ppm/C; Value_Code: 47k5; Value: 47.5k; EIA_Code: E96; SizeX_mm: 1; SizeY_mm: 0.5; SizeZ_mm: 0.6; Value2: 0.063W; AEC Qualified: Y; VDC_V: 50V; AEC Category: Q200; AEC Grade: 0
R39 R40 R42 R45 = CMP-0027275-3: RES, 33.2, 1%, 0.05 W, 0201; Manufacturer: Vishay-Dale; Power_W: 50mW; TempCo: 200 ppm/C; Value_Code: 33R2; Value: 33.2; EIA_Code: E96; SizeX_mm: 0.6; SizeY_mm: 0.3; SizeZ_mm: 0.26; Value2: 0.05W; SizeArea_mm2: 0.18; AEC Qualified: N; AEC Category: Q200
R41 R43 = CMP-0025958-3: as R13 on sheet PROC051B_DUT_Reference
R44 = CMP-0027275-3: RES, 33.2, 1%, 0.05 W, 0201; Manufacturer: Vishay-Dale; Power_W: 50mW; TempCo: 200 ppm/C; Value_Code: 33R2; Value: 33.2; EIA_Code: E96; SizeX_mm: 0.6; SizeY_mm: 0.3; SizeZ_mm: 0.26; Value2: 0.05W; SizeArea_mm2: 0.18; CompType: Resistor; AEC Qualified: N; AEC Category: Q200
U1 = CMP-0079267-1: 2.3V-3.6V, 16M-BIT [x 1/x 2/x 4] CMOS FLASH Memory, WSON-8; Manufacturer: Macronix International Co., LTD; SizeArea_mm2: 30; SizeAreaWB_mm2: 56; SizeY_mm: 5; SizeZ_mm: 0.8; SizeX_mm: 6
